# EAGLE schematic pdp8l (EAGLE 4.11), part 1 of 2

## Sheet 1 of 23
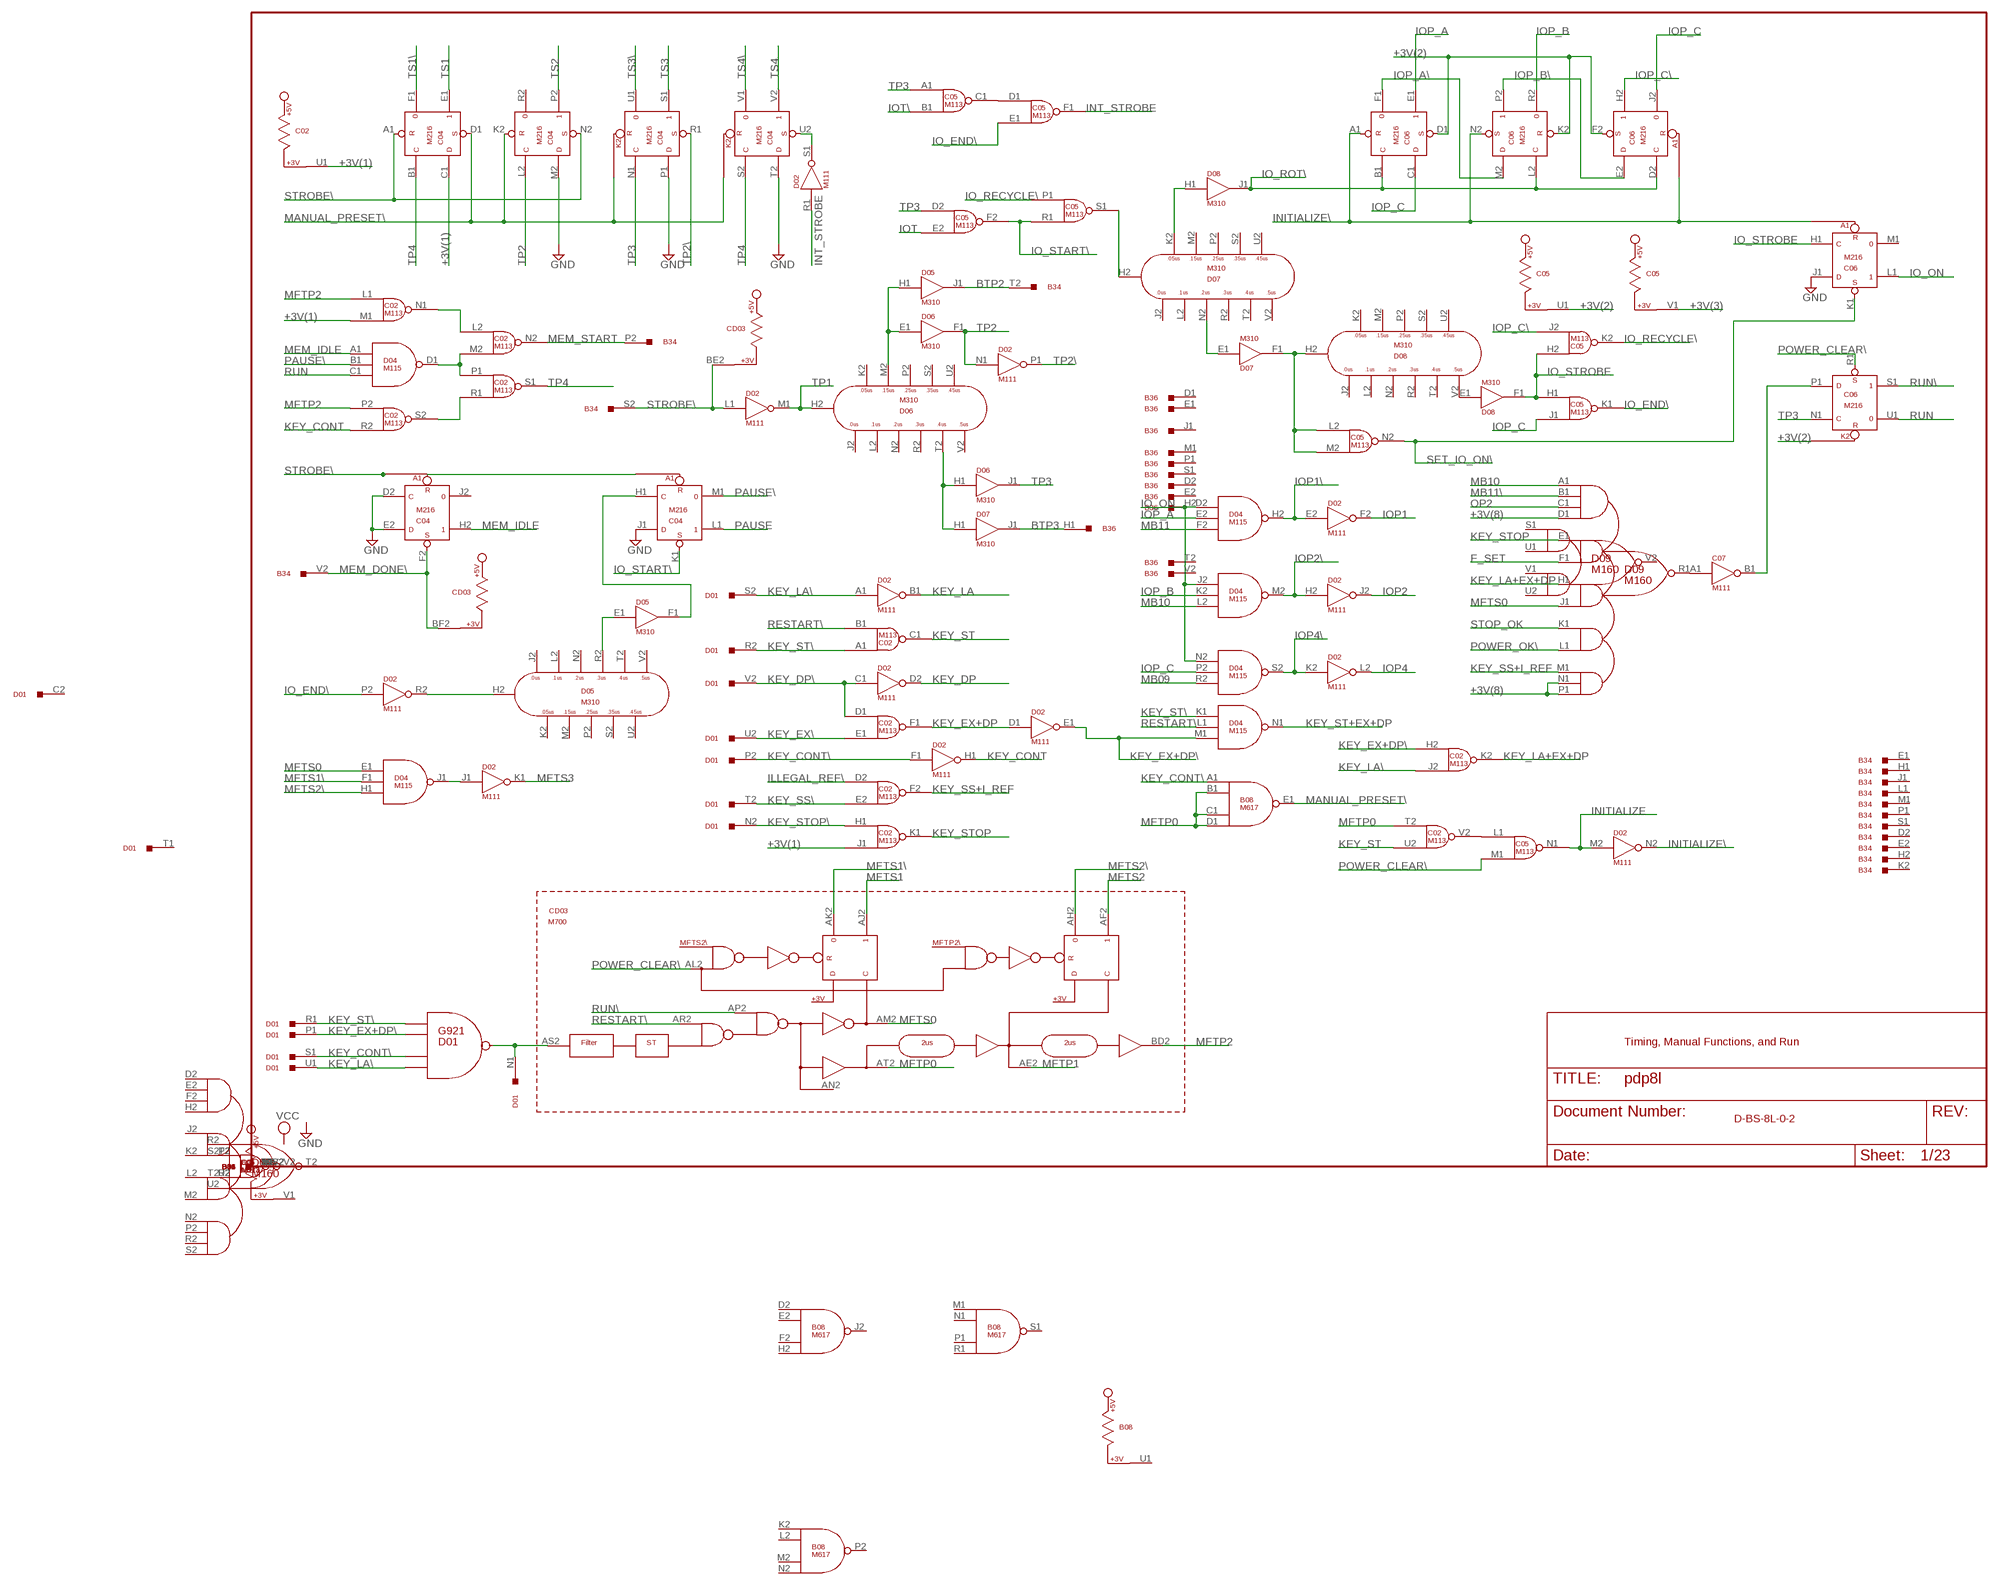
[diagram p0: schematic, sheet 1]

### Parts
B08  M617  [H807]
B34  M903  [H807]
B36  M903  [H807]
C02  M113  [H807]
C04  M216  M206X  [H807]
C05  M113  [H807]
C06  M216  M206X  [H807]
C07  M111  [H807]
CD03  M700  [H807-2]
D01  G921  M916  [H807]
D02  M111  [H807]
D04  M115  [H807]
D05  M310  [H807]
D06  M310  [H807]
D07  M310  [H807]
D08  M310  [H807]
D09  M160  [H807]

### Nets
+3V(1): C02.J1(K1:IN2) C02.M1(N1:IN2) C02.U1 C04.C1(E1:D) ; also sheet 2
+3V(2): C05.U1 C06.D1(E1:S) C06.F2(H2:S) C06.K2(P2:R)
+3V(3): C05.V1 ; also sheet 2
+3V(8): D09.D1(R1:IN1D) D09.N1(R1:IN5B) D09.P1(R1:IN5C) ; also sheet 3
BTP2: B34.T2 D05.J1(J1:OUT)
BTP3: B36.H1 D07.J1(J1:OUT)
F_SET: D09.F1(R1:IN2B) ; also sheet 2,3,6
GND [Supply]: C04.D2(H2:C) C04.E2(H2:D) C04.J1(L1:D) C04.M2(P2:D) C04.P1(S1:D) C04.T2(V2:D) C06.J1(L1:D) ; also sheet 3,8,9,10,11,12,13,14,15,16,19,20,21,23
ILLEGAL_REF\: C02.D2(F2:IN1) ; also sheet 2,5
INITIALIZE: C05.N1(N1:OUT) D02.M2(N2:IN) ; also sheet 12,13,14
INITIALIZE\: C06.A1(E1:R) C06.N2(P2:S) D02.N2(N2:OUT) ; also sheet 12,21,22
INT_STROBE: C05.F1(F1:OUT) D02.R1(S1:IN) ; also sheet 6
IO_END\: C05.E1(F1:IN2) C05.K1(K1:OUT) D02.P2(R2:IN)
IO_ON: C06.L1 D04.D2(H2:IN1) D04.J2(M2:IN1) D04.N2(S2:IN1)
IO_RECYCLE\: C05.K2(K2:OUT) C05.P1(S1:IN1)
IO_ROT\: C06.B1(E1:C) C06.D2(H2:C) C06.L2(P2:C) D08.J1(J1:OUT)
IO_START\: C04.K1(L1:S) C05.F2(F2:OUT) C05.R1(S1:IN2)
IO_STROBE: C05.H1(K1:IN1) C05.H2(K2:IN1) C06.H1(L1:C) D08.F1(F1:OUT) ; also sheet 5
IOP1: D02.F2(F2:OUT) ; also sheet 13,14,21,22,23
IOP1\: D02.E2(F2:IN) D04.H2(H2:OUT) ; also sheet 3,12
IOP2: D02.J2(J2:OUT) ; also sheet 13,14,20,21,22
IOP2\: D02.H2(J2:IN) D04.M2(M2:OUT) ; also sheet 3,12
IOP4: D02.L2(L2:OUT) ; also sheet 13,14,21,22,23
IOP4\: D02.K2(L2:IN) D04.S2(S2:OUT) ; also sheet 3,12
IOP_A: C06.E1 D04.E2(H2:IN2)
IOP_A\: C06.F1 C06.M2(P2:D)
IOP_B: C06.R2 D04.K2(M2:IN2)
IOP_B\: C06.E2(H2:D) C06.P2
IOP_C: C05.J1(K1:IN2) C06.C1(E1:D) C06.J2 D04.P2(S2:IN2)
IOP_C\: C05.J2(K2:IN2) C06.H2
IOT: C05.E2(F2:IN2) ; also sheet 2,6
IOT\: C05.B1(C1:IN2) ; also sheet 2
KEY_CONT: C02.R2(S2:IN2) D02.H1(H1:OUT)
KEY_CONT\: B08.A1(E1:IN1) D01.P2 D01.S1 D02.F1(H1:IN) ; also sheet 5
KEY_DP: D02.D2(D2:OUT) ; also sheet 3
KEY_DP\: C02.D1(F1:IN1) D01.V2 D02.C1(D2:IN)
KEY_EX+DP: C02.F1(F1:OUT) D02.D1(E1:IN) ; also sheet 3,4
KEY_EX+DP\: C02.H2(K2:IN1) D01.P1 D02.E1(E1:OUT) D04.M1(N1:IN3)
KEY_EX\: C02.E1(F1:IN2) D01.U2
KEY_LA: D02.B1(B1:OUT) ; also sheet 3,19
KEY_LA+EX+DP: C02.K2(K2:OUT) D09.H1(R1:IN3A) ; also sheet 5
KEY_LA\: C02.J2(K2:IN2) D01.S2 D01.U1 D02.A1(B1:IN) ; also sheet 19
KEY_SS+I_REF: C02.F2(F2:OUT) D09.M1(R1:IN5A)
KEY_SS\: C02.E2(F2:IN2) D01.T2
KEY_ST: C02.C1(C1:OUT) C02.U2(V2:IN2) ; also sheet 2,3
KEY_ST+EX+DP: D04.N1(N1:OUT) ; also sheet 3
KEY_ST\: C02.A1(C1:IN1) D01.R1 D01.R2 D04.K1(N1:IN1)
KEY_STOP: C02.K1(K1:OUT) D09.E1(R1:IN2A)
KEY_STOP\: C02.H1(K1:IN1) D01.N2
MANUAL_PRESET\: B08.E1(E1:OUT) C04.D1(E1:S) C04.K2(P2:R) ; also sheet 2,6
MB09: D04.R2(S2:IN3) ; also sheet 3,4,7,12,23
MB10: D04.L2(M2:IN3) D09.A1(R1:IN1A) ; also sheet 4,7,12,23
MB11: D04.F2(H2:IN3) ; also sheet 4,7,12,23
MB11\: D09.B1(R1:IN1B) ; also sheet 2,3,6,7,16,23
MEM_DONE\: B34.V2 C04.F2(H2:S) CD03.BF2 ; also sheet 6,15
MEM_IDLE: C04.H2 D04.A1(D1:IN1)
MEM_START: B34.P2 C02.N2(N2:OUT) ; also sheet 15
MFTP0: B08.B1(E1:IN2) B08.C1(E1:IN3) B08.D1(E1:IN4) C02.T2(V2:IN1) CD03.AT2(CT2) ; also sheet 19
MFTP1: CD03.AE2(CE2) ; also sheet 5,19
MFTP2: C02.L1(N1:IN1) C02.P2(S2:IN1) CD03.BD2(DD2) ; also sheet 2,5
MFTS0: CD03.AM2(CM2) D04.E1(J1:IN1) D09.J1(R1:IN3B)
MFTS1: CD03.AJ2(CJ2) ; also sheet 3
MFTS1\: CD03.AK2(CK2) D04.F1(J1:IN2) ; also sheet 3
MFTS2: CD03.AF2(CF2) ; also sheet 3,4
MFTS2\: CD03.AH2(CH2) D04.H1(J1:IN3) ; also sheet 3
MFTS3: D02.K1(K1:OUT) ; also sheet 3
N$1: C02.R1(S1:IN2) C02.S2(S2:OUT)
N$2: C02.L2(N2:IN1) C02.N1(N1:OUT)
N$3: C02.M2(N2:IN2) C02.P1(S1:IN1) D04.D1(D1:OUT)
N$4: D05.E1(F1:IN) D05.R2(H2:R2)
N$5: D02.R2(R2:OUT) D05.H2(H2:H2)
N$6: C04.H1(L1:C) D05.F1(F1:OUT)
N$7: D02.J1(K1:IN) D04.J1(J1:OUT)
N$8: D05.H1(J1:IN) D06.E1(F1:IN) D06.M2(H2:M2)
N$9: D06.H1(J1:IN) D06.T2(H2:T2) D07.H1(J1:IN)
N$10: C05.S1(S1:OUT) D07.H2(H2:H2)
N$11: C04.U2(V2:S) D02.S1(S1:OUT)
N$12: C05.C1(C1:OUT) C05.D1(F1:IN1)
N$13: D07.K2(H2:K2) D08.H1(J1:IN)
N$14: D07.E1(F1:IN) D07.N2(H2:N2)
N$15: C05.L2(N2:IN1) C05.M2(N2:IN2) D07.F1(F1:OUT) D08.H2(H2:H2)
N$16: D08.E1(F1:IN) D08.V2(H2:V2)
N$19: C07.A1(B1:IN) D09.R1(R1:OUT)
N$20: C06.P1(S1:D) C07.B1(B1:OUT)
N$21: C02.V2(V2:OUT) C05.L1(N1:IN1)
N$22: CD03.AS2(CS2) D01.N1
OP2: D09.C1(R1:IN1C) ; also sheet 2,3,5
PAUSE: C04.L1 ; also sheet 3
PAUSE\: C04.M1 D04.B1(D1:IN2)
POWER_CLEAR\: C05.M1(N1:IN2) C06.R1(S1:S) CD03.AL2(CL2) ; also sheet 15
POWER_OK\: D09.L1(R1:IN4B) ; also sheet 15
RESTART\: C02.B1(C1:IN2) CD03.AR2(CR2) D04.L1(N1:IN2) ; also sheet 3,19,20
RUN: C06.U1 D04.C1(D1:IN3)
RUN\: C06.S1 CD03.AP2(CP2) ; also sheet 12
SET_IO_ON\: C05.N2(N2:OUT) C06.K1(L1:S) ; also sheet 5
STOP_OK: D09.K1(R1:IN4A) ; also sheet 15,20
STROBE\: B34.S2 C04.A1(E1:R) C04.N2(P2:S) CD03.BE2 D02.L1(M1:IN) ; also sheet 6,15
TP1: D02.M1(M1:OUT) D06.H2(H2:H2) ; also sheet 2,5,6
TP2: C04.L2(P2:C) D02.N1(P1:IN) D06.F1(F1:OUT) ; also sheet 2,5,6
TP2\: C04.R1(S1:S) D02.P1(P1:OUT) ; also sheet 5
TP3: C04.N1(S1:C) C05.A1(C1:IN1) C05.D2(F2:IN1) C06.N1(S1:C) D06.J1(J1:OUT) ; also sheet 5,23
TP4: C02.S1(S1:OUT) C04.B1(E1:C) C04.S2(V2:C) ; also sheet 2,5,6
TS1: C04.E1 ; also sheet 3,4
TS1\: C04.F1 ; also sheet 12
TS2: C04.P2 ; also sheet 2,3,4,5
TS3: C04.S1 ; also sheet 2,3,4
TS3\: C04.U1 ; also sheet 12
TS4: C04.V2 ; also sheet 3,19
TS4\: C04.V1 ; also sheet 3
Unconnected: B34.M2 B36.K2 B36.M2 B36.P2 C02.V1 C04.J2 C04.R2 CD03.AN2(CN2) D01.A1 D01.B1 D01.B2 D01.C1 D01.D1 D01.E1 D01.F1 D01.H1 D01.H2 D01.J1 D01.K1 D01.L1 D01.M1 D05.J2(H2:J2) D05.K2(H2:K2) D05.L2(H2:L2) D05.M2(H2:M2) D05.N2(H2:N2) D05.P2(H2:P2) D05.S2(H2:S2) D05.T2(H2:T2) D05.U2(H2:U2) D05.V2(H2:V2) D06.J2(H2:J2) D06.K2(H2:K2) D06.L2(H2:L2) D06.N2(H2:N2) D06.P2(H2:P2) D06.R2(H2:R2) D06.S2(H2:S2) D06.U2(H2:U2) D06.V2(H2:V2) D07.J2(H2:J2) D07.L2(H2:L2) D07.M2(H2:M2) D07.P2(H2:P2) D07.R2(H2:R2) D07.S2(H2:S2) D07.T2(H2:T2) D07.U2(H2:U2) D07.V2(H2:V2) D08.J2(H2:J2) D08.K2(H2:K2) D08.L2(H2:L2) D08.M2(H2:M2) D08.N2(H2:N2) D08.P2(H2:P2) D08.R2(H2:R2) D08.S2(H2:S2) D08.T2(H2:T2) D08.U2(H2:U2)

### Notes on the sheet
- G921
- D01 | Timing, Manual Functions, and Run
- D-BS-8L-0-2

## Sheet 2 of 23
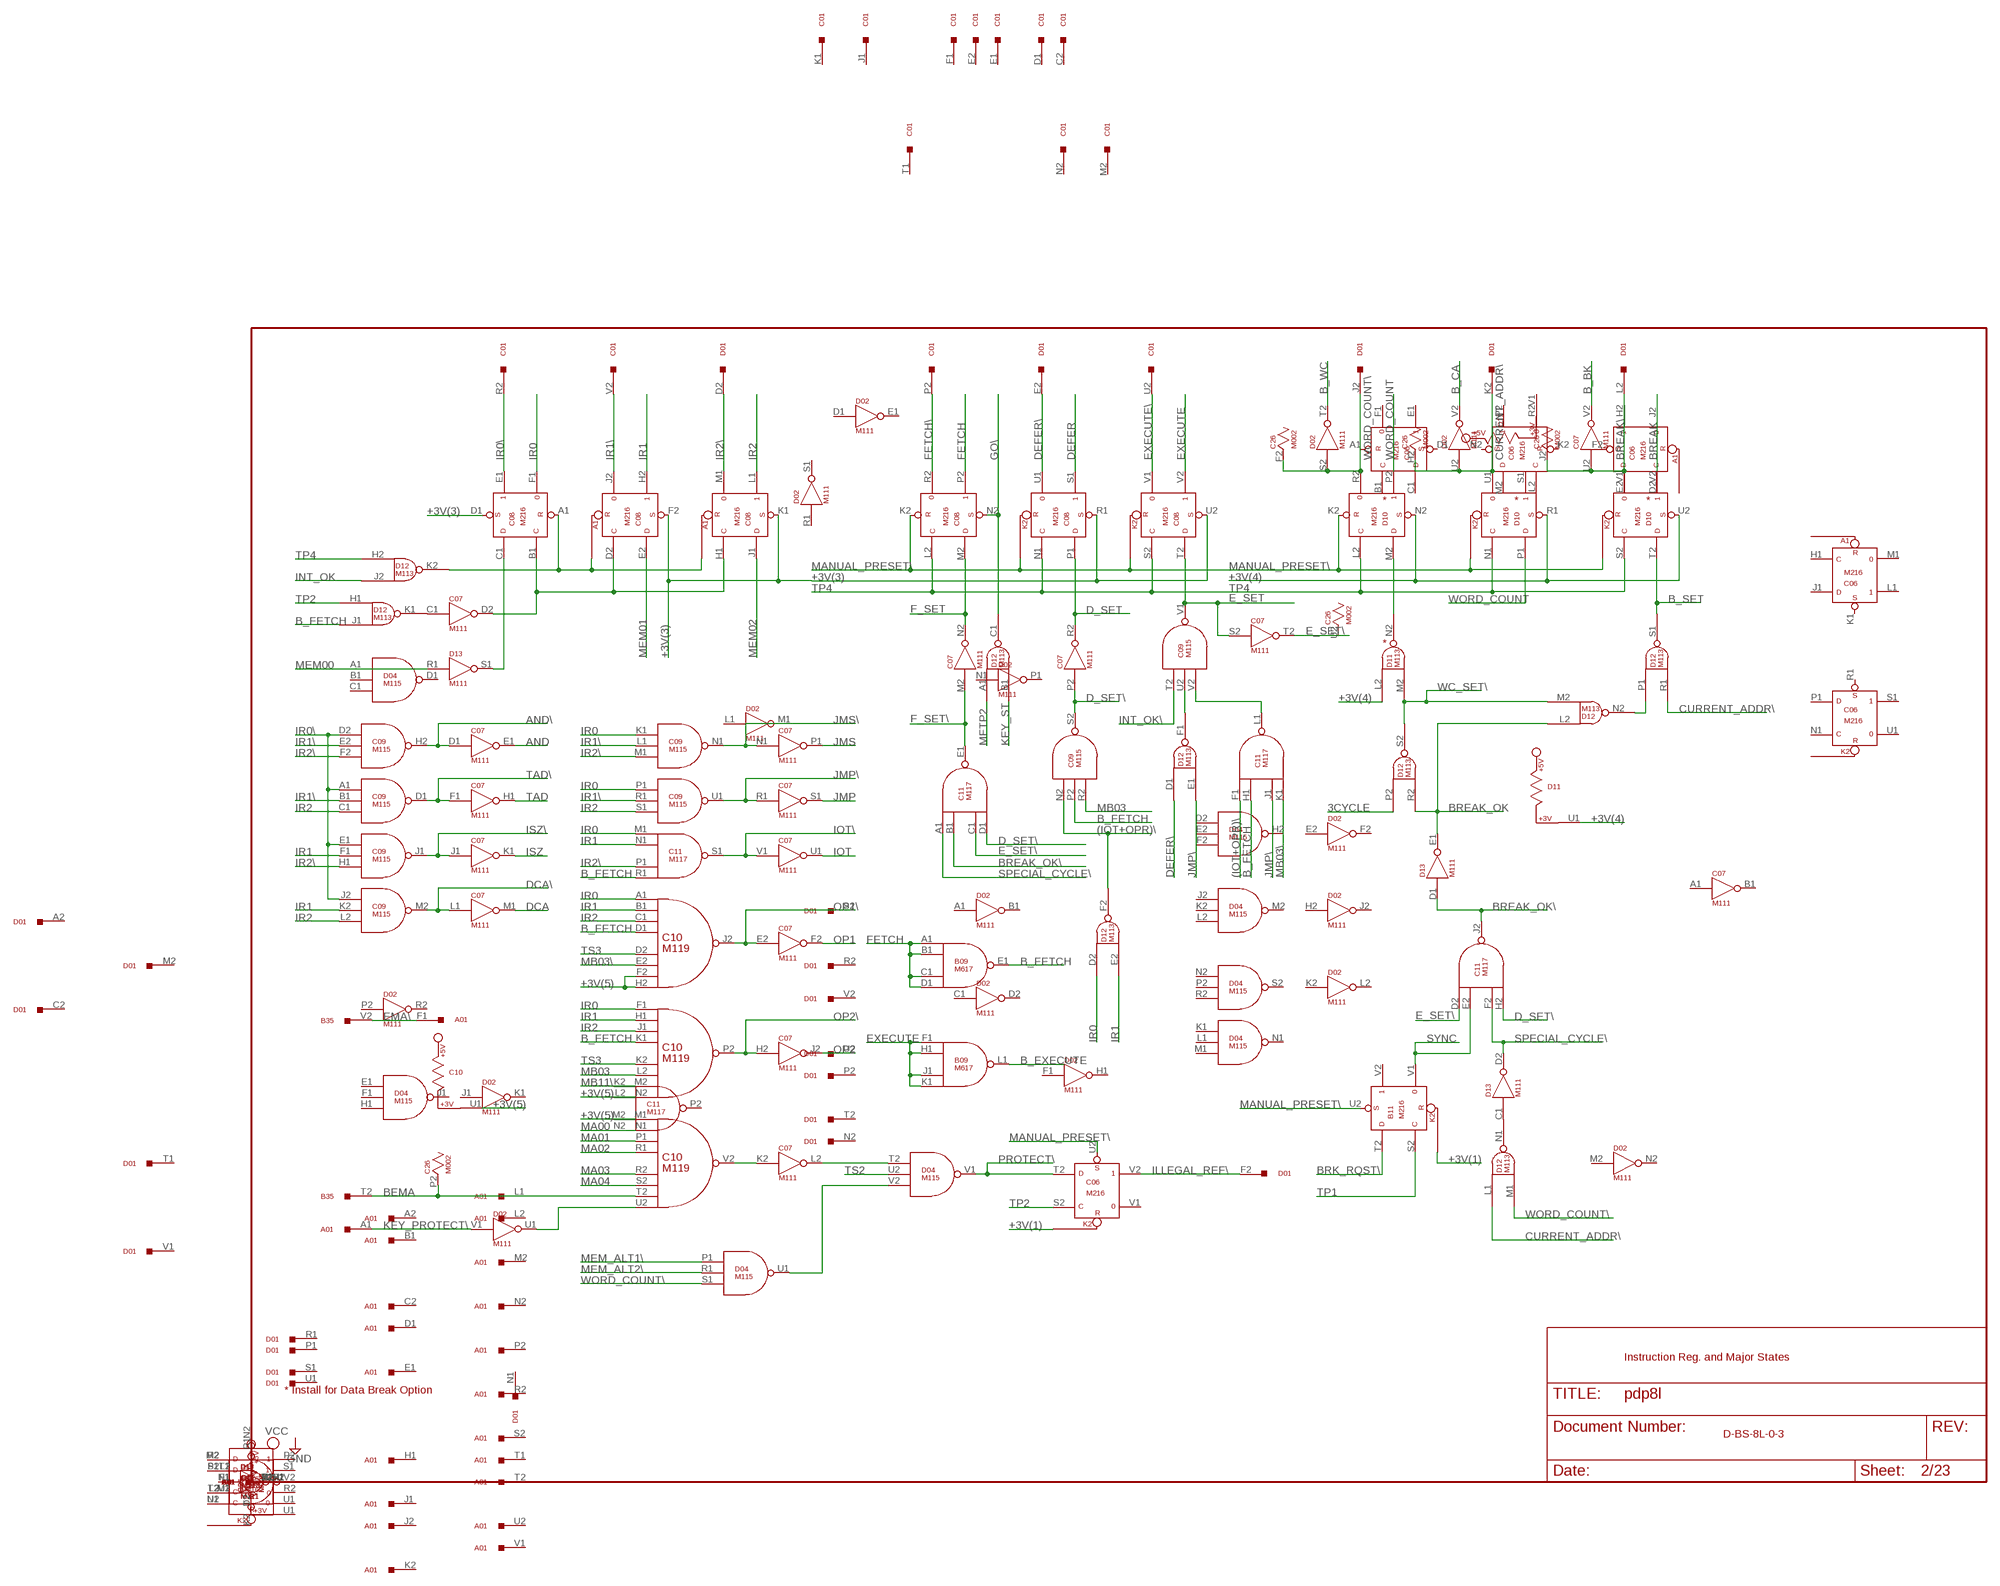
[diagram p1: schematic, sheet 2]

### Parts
A01  G921  M916  [H807]
B09  M617  [H807]
B11  M216  M206X  [H807]
B35  M903  [H807]
C01  G921  M916  [H807]
C08  M216  M206X  [H807]
C09  M115  [H807]
C10  M119  [H807]
C11  M117  [H807]
C26  M002  [H807]
D10  M216  M206X  [H807]
D11  M113  [H807]
D12  M113  [H807]
D13  M111  [H807]

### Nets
3CYCLE: D12.P2(S2:IN1) ; also sheet 12
(IOT+OPR)\: C09.N2(S2:IN1) C11.F1(L1:IN1) D12.F2(F2:OUT)
+3V(3): C08.D1(E1:S) C08.F2(H2:S) C08.K1(L1:S) C08.R1(S1:S) C08.U2(V2:S) ; also sheet 1
+3V(4): D10.N2(P2:S) D10.R1(S1:S) D10.U2(V2:S) D11.L2(N2:IN1) D11.U1 ; also sheet 6
+3V(5): C10.F2(J2:IN7) C10.H2(J2:IN8) C10.M1(V2:IN1) C10.N2(P2:IN8) C10.U1
AND: C07.E1(E1:OUT) ; also sheet 4
AND\: C07.D1(E1:IN) C09.H2(H2:OUT) ; also sheet 5
B_BK: C07.V2(V2:OUT) ; also sheet 3,4
B_CA: D02.V2(V2:OUT) ; also sheet 3,4
B_EXECUTE: B09.L1(L1:OUT) ; also sheet 3,4,5
B_FETCH: B09.E1(E1:OUT) C09.P2(S2:IN2) C10.D1(J2:IN4) C10.K1(P2:IN4) C11.H1(L1:IN2) C11.R1(S1:IN4) D12.J1(K1:IN2) ; also sheet 3,5,6
B_SET: D10.T2(V2:D) D12.S1(S1:OUT) ; also sheet 19
B_WC: D02.T2(T2:OUT) ; also sheet 3
BEMA: B35.T2 C10.T2(V2:IN7) C26.P2
BREAK: D10.V2 ; also sheet 6
BREAK\: C07.U2(V2:IN) C26.J2 D01.L2 D10.V1 ; also sheet 12
BREAK_OK: D12.L2(N2:IN1) D12.R2(S2:IN2) D13.E1(E1:OUT) ; also sheet 3
BREAK_OK\: C11.B1(E1:IN2) C11.J2(J2:OUT) D13.D1(E1:IN) ; also sheet 6
BRK_RQST\: B11.T2(V2:D) ; also sheet 12
CURRENT_ADDR\: C26.H2 D01.K2 D02.U2(V2:IN) D10.U1 D12.L1(N1:IN1) D12.R1(S1:IN2)
D_SET: C07.R2(R2:OUT) C08.P1(S1:D)
D_SET\: C07.P2(R2:IN) C09.S2(S2:OUT) C11.D1(E1:IN4) C11.H2(J2:IN4) ; also sheet 3
DCA: C07.M1(M1:OUT) ; also sheet 3
DCA\: C07.L1(M1:IN) C09.M2(M2:OUT) ; also sheet 5
DEFER: C08.S1 ; also sheet 3,4,5,19
DEFER\: C08.U1 D01.E2 D12.D1(F1:IN1)
E_SET: C07.S2(T2:IN) C08.T2(V2:D) C09.V1(V1:OUT)
E_SET\: C07.T2(T2:OUT) C11.C1(E1:IN3) C11.D2(J2:IN1) ; also sheet 3,19
EMA\: A01.F1 B35.V2
EXECUTE: B09.F1(L1:IN1) B09.H1(L1:IN2) B09.J1(L1:IN3) B09.K1(L1:IN4) C08.V2
EXECUTE\: C01.U2 C08.V1
F_SET: C07.N2(N2:OUT) C08.M2(P2:D) ; also sheet 1,3,6
F_SET\: C07.M2(N2:IN) C11.E1(E1:OUT) ; also sheet 19
FETCH: B09.A1(E1:IN1) B09.B1(E1:IN2) B09.C1(E1:IN3) B09.D1(E1:IN4) C08.P2 ; also sheet 4
FETCH\: C01.P2 C08.R2
GO\: C08.N2(P2:S) D12.C1(C1:OUT) ; also sheet 5,6
ILLEGAL_REF\: C06.V2 D01.F2 ; also sheet 1,5
INT_OK: D12.J2(K2:IN2) ; also sheet 6,19
INT_OK\: C09.T2(V1:IN1) ; also sheet 3,6
IOT: C07.U1(U1:OUT) ; also sheet 1,6
IOT\: C07.V1(U1:IN) C11.S1(S1:OUT) ; also sheet 1
IR0: C08.F1 C09.K1(N1:IN1) C09.P1(U1:IN1) C10.A1(J2:IN1) C10.F1(P2:IN1) C11.M1(S1:IN1) D12.D2(F2:IN1)
IR0\: C01.R2 C08.E1 C09.A1(D1:IN1) C09.D2(H2:IN1) C09.E1(J1:IN1) C09.J2(M2:IN1) ; also sheet 19
IR1: C08.H2 C09.F1(J1:IN2) C09.K2(M2:IN2) C10.B1(J2:IN2) C10.H1(P2:IN2) C11.N1(S1:IN2) D12.E2(F2:IN2)
IR1\: C01.V2 C08.J2 C09.B1(D1:IN2) C09.E2(H2:IN2) C09.L1(N1:IN2) C09.R1(U1:IN2)
IR2: C08.L1 C09.C1(D1:IN3) C09.L2(M2:IN3) C09.S1(U1:IN3) C10.C1(J2:IN3) C10.J1(P2:IN3)
IR2\: C08.M1 C09.F2(H2:IN3) C09.H1(J1:IN3) C09.M1(N1:IN3) C11.P1(S1:IN3) D01.D2
ISZ: C07.K1(K1:OUT) ; also sheet 4,5
ISZ\: C07.J1(K1:IN) C09.J1(J1:OUT)
JMP: C07.S1(S1:OUT) ; also sheet 3,5
JMP\: C07.R1(S1:IN) C09.U1(U1:OUT) C11.J1(L1:IN3) D12.E1(F1:IN2) ; also sheet 3,19
JMS: C07.P1(P1:OUT) ; also sheet 3,4,5
JMS\: C07.N1(P1:IN) C09.N1(N1:OUT) ; also sheet 19
KEY_PROTECT\: A01.A1 D02.V1(U1:IN)
KEY_ST: D12.B1(C1:IN2) ; also sheet 1,3
MA00: C10.N1(V2:IN2) ; also sheet 7,17
MA01: C10.P1(V2:IN3) ; also sheet 7,17
MA02: C10.R1(V2:IN4) ; also sheet 7,17
MA03: C10.R2(V2:IN5) ; also sheet 7,17
MA04: C10.S2(V2:IN6) ; also sheet 7,17
MANUAL_PRESET\: B11.U2(V2:S) C06.U2(V2:S) C08.K2(P2:R) D10.K2(P2:R) ; also sheet 1,6
MB03: C09.R2(S2:IN3) C10.L2(P2:IN6) ; also sheet 7,12,23
MB03\: C10.E2(J2:IN6) C11.K1(L1:IN4) ; also sheet 3,6,7,12,13,14,16,20,21,22,23
MB11\: C10.M2(P2:IN7) ; also sheet 1,3,6,7,16,23
MEM00: D13.R1(S1:IN) ; also sheet 8,16,23
MEM01: C08.E2(H2:D) ; also sheet 8,16,23
MEM02: C08.J1(L1:D) ; also sheet 8,16,23
MEM_ALT1\: D04.P1(U1:IN1) ; also sheet 3
MEM_ALT2\: D04.R1(U1:IN2) ; also sheet 4
MFTP2: D12.A1(C1:IN1) ; also sheet 1,5
N$23: C07.C1(D2:IN) D12.K1(K1:OUT)
N$24: D10.M2(P2:D) D11.N2(N2:OUT)
N$25: D12.N2(N2:OUT) D12.P1(S1:IN1)
N$26: C07.D2(D2:OUT) C08.B1(E1:C) C08.D2(H2:C) C08.H1(L1:C)
N$27: C08.A1(E1:R) D12.K2(K2:OUT)
N$28: C08.C1(E1:D) D13.S1(S1:OUT)
N$29: C10.U2(V2:IN8) D02.U1(U1:OUT)
N$30: C07.L2(L2:OUT) D04.T2(V1:IN1)
N$31: D04.U1(U1:OUT) D04.V2(V1:IN3)
N$32: C07.K2(L2:IN) C10.V2(V2:OUT)
N$36: D12.N1(N1:OUT) D13.C1(D2:IN)
N$37: C09.U2(V1:IN2) D12.F1(F1:OUT)
N$38: C09.V2(V1:IN3) C11.L1(L1:OUT)
OP1: C07.F2(F2:OUT) ; also sheet 3,4
OP1\: C07.E2(F2:IN) C10.J2(J2:OUT) ; also sheet 5
OP2: C07.J2(J2:OUT) ; also sheet 1,3,5
OP2\: C07.H2(J2:IN) C10.P2(P2:OUT) ; also sheet 5
PROTECT\: C06.T2(V2:D) D04.V1(V1:OUT) ; also sheet 3,4
SPECIAL_CYCLE\: C11.A1(E1:IN1) C11.F2(J2:IN3) D13.D2(D2:OUT)
SYNC: B11.V1 C11.E2(J2:IN2)
TAD: C07.H1(H1:OUT) ; also sheet 3
TAD\: C07.F1(H1:IN) C09.D1(D1:OUT) ; also sheet 5
TP1: B11.S2(V2:C) ; also sheet 1,5,6
TP2: C06.S2(V2:C) D12.H1(K1:IN1) ; also sheet 1,5,6
TP4: C08.L2(P2:C) C08.N1(S1:C) C08.S2(V2:C) D10.L2(P2:C) D10.N1(S1:C) D10.S2(V2:C) D12.H2(K2:IN1) ; also sheet 1,5,6
TS2: D04.U2(V1:IN2) ; also sheet 1,3,4,5
TS3: C10.D2(J2:IN5) C10.K2(P2:IN5) ; also sheet 1,3,4
WC_SET\: D11.M2(N2:IN2) D12.M2(N2:IN2) D12.S2(S2:OUT) ; also sheet 19
WORD_COUNT: D10.P1(S1:D) D10.P2
WORD_COUNT\: C26.F2 D01.J2 D02.S2(T2:IN) D04.S1(U1:IN3) D10.R2 D12.M1(N1:IN2) ; also sheet 4,6,19
Unconnected: A01.M1 A01.N1 A01.P1 A01.R1 A01.S1 A01.U1 A01.V2 B11.V2 B35.M2 B35.P2 B35.S2 C01.A1 C01.B1 C01.B2 C01.C1 C01.D2 C01.L1 C01.M1 C01.N1 C01.P1 C01.R1 C01.S1 C01.T2 C01.U1 C06.M1 C06.V1 C10.V1 C11.U1 C11.V1 C26.K2 C26.L2 C26.M2 C26.N2 D10.H1(L1:C) D10.J1(L1:D) D10.K1(L1:S) D10.L1 D10.M1 D10.S1 D12.U1 D12.V1

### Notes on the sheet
- * | * | *
- *
- Instruction Reg. and Major States
- * Install for Data Break Option
- D-BS-8L-0-3

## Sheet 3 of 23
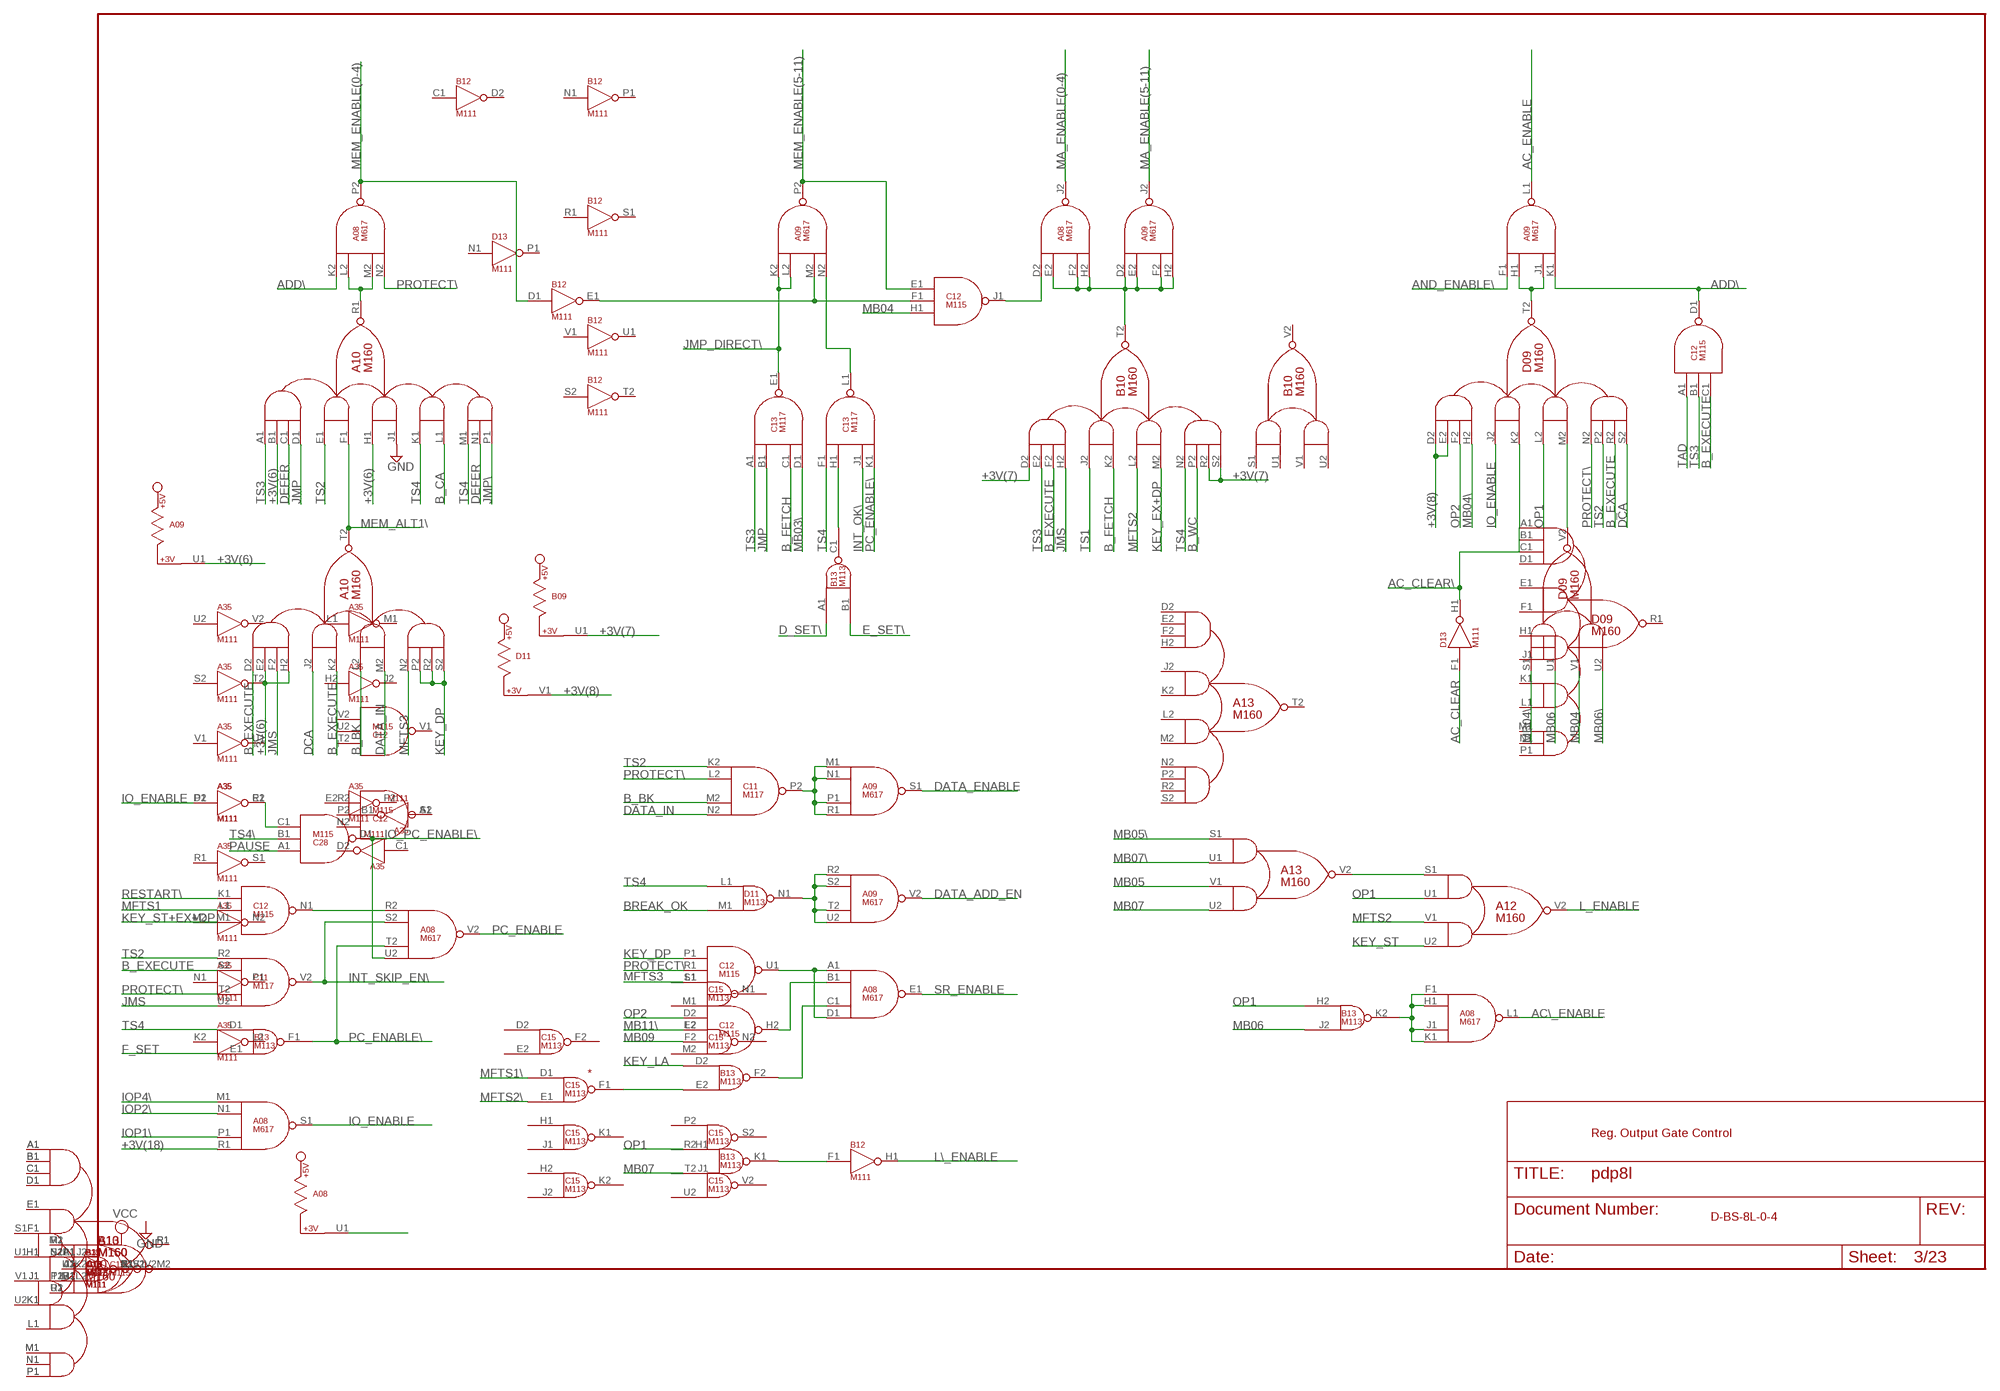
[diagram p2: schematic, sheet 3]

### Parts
A08  M617  [H807]
A09  M617  [H807]
A10  M160  [H807]
A12  M160  [H807]
A13  M160  [H807]
A35  M111  [H807]
B10  M160  [H807]
B12  M111  [H807]
B13  M113  [H807]
C12  M115  [H807]
C13  M117  [H807]
C15  M113  [H807]
C28  M115  [H807]

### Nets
+3V(6): A09.U1 A10.B1(R1:IN1B) A10.E2(T2:IN1B) A10.H1(R1:IN3A) A10.H2(T2:IN1D)
+3V(7): B09.U1 B10.D2(T2:IN1A) B10.R2(T2:IN4C) B10.S2(T2:IN4D)
+3V(8): D09.D2(T2:IN1A) D09.E2(T2:IN1B) D11.V1 ; also sheet 1
+3V(18): A08.R1(S1:IN4) A08.U1
AC\_ENABLE: A08.L1(L1:OUT) ; also sheet 8,9,10,11
AC_CLEAR: D13.F1(H1:IN) ; also sheet 12
AC_CLEAR\: D09.K2(T2:IN2B) D13.H1(H1:OUT)
AC_ENABLE: A09.L1(L1:OUT) ; also sheet 8,9,10,11
ADD\: A08.K2(P2:IN1) A09.K1(L1:IN4) C12.D1(D1:OUT)
AND_ENABLE\: A09.F1(L1:IN1) ; also sheet 4
B_BK: A10.L2(T2:IN3A) C11.M2(P2:IN3) ; also sheet 2,4
B_CA: A10.L1(R1:IN4B) ; also sheet 2,4
B_EXECUTE: A10.D2(T2:IN1A) A10.K2(T2:IN2B) B10.F2(T2:IN1C) C11.S2(V2:IN2) C12.C1(D1:IN3) D09.R2(T2:IN4C) ; also sheet 2,4,5
B_FETCH: B10.K2(T2:IN2B) C13.C1(E1:IN3) ; also sheet 2,5,6
B_WC: B10.P2(T2:IN4B) ; also sheet 2
BREAK_OK: D11.M1(N1:IN2) ; also sheet 2
D_SET\: B13.A1(C1:IN1) ; also sheet 2
DATA_ADD_EN: A09.V2(V2:OUT) ; also sheet 8,9,10,11
DATA_ENABLE: A09.S1(S1:OUT) ; also sheet 8,9,10,11
DATA_IN: A10.M2(T2:IN3B) C11.N2(P2:IN4) ; also sheet 12
DCA: A10.J2(T2:IN2A) D09.S2(T2:IN4D) ; also sheet 2
DEFER: A10.C1(R1:IN1C) A10.N1(R1:IN5B) ; also sheet 2,4,5,19
E_SET\: B13.B1(C1:IN2) ; also sheet 2,19
F_SET: B13.E1(F1:IN2) ; also sheet 1,2,6
GND [Supply]: A10.J1(R1:IN3B) ; also sheet 1,8,9,10,11,12,13,14,15,16,19,20,21,23
INT_OK\: C13.J1(L1:IN3) ; also sheet 2,6
INT_SKIP_EN\: A08.S2(V2:IN2) C11.V2(V2:OUT) ; also sheet 4
IO_ENABLE: A08.S1(S1:OUT) A35.D1(E1:IN) D09.J2(T2:IN2A) ; also sheet 5,8,9,10,11
IO_PC_ENABLE\: A08.U2(V2:IN4) C28.D1(D1:OUT) ; also sheet 4
IOP1\: A08.P1(S1:IN3) ; also sheet 1,12
IOP2\: A08.N1(S1:IN2) ; also sheet 1,12
IOP4\: A08.M1(S1:IN1) ; also sheet 1,12
JMP: A10.D1(R1:IN1D) C13.B1(E1:IN2) ; also sheet 2,5
JMP\: A10.P1(R1:IN5C) ; also sheet 2,19
JMP_DIRECT\: A09.K2(P2:IN1) A09.L2(P2:IN2) C13.E1(E1:OUT) ; also sheet 5
JMS: A10.F2(T2:IN1C) B10.H2(T2:IN1D) C11.U2(V2:IN4) ; also sheet 2,4,5
KEY_DP: A10.P2(T2:IN4B) A10.R2(T2:IN4C) A10.S2(T2:IN4D) C12.P1(U1:IN1) ; also sheet 1
KEY_EX+DP: B10.M2(T2:IN3B) ; also sheet 1,4
KEY_LA: B13.D2(F2:IN1) ; also sheet 1,19
KEY_ST: A12.U2(V2:IN2B) ; also sheet 1,2
KEY_ST+EX+DP: C12.M1(N1:IN3) ; also sheet 1
L\_ENABLE: B12.H1(H1:OUT) ; also sheet 7
L_ENABLE: A12.V2(V2:OUT) ; also sheet 7
MA_ENABLE(0-4): A08.J2(J2:OUT) ; also sheet 8,9
MA_ENABLE(5-11): A09.J2(J2:OUT) ; also sheet 9,10,11
MB03\: C13.D1(E1:IN4) ; also sheet 2,6,7,12,13,14,16,20,21,22,23
MB04: C12.H1(J1:IN3) D09.V1(V2:IN2A) ; also sheet 7,12,23
MB04\: D09.H2(T2:IN1D) D09.S1(V2:IN1A) ; also sheet 6,7,12,13,14,20,21,22,23
MB05: A13.V1(V2:IN2A) ; also sheet 5,7,12,20,23
MB05\: A13.S1(V2:IN1A) ; also sheet 6,7,12,13,14,21,22,23
MB06: B13.J2(K2:IN2) D09.U1(V2:IN1B) ; also sheet 5,7,12,14,23
MB06\: D09.U2(V2:IN2B) ; also sheet 6,7,12,13,20,21,22,23
MB07: A13.U2(V2:IN2B) B13.J1(K1:IN2) ; also sheet 5,7,12,13,21,23
MB07\: A13.U1(V2:IN1B) ; also sheet 6,7,12,14,20,22,23
MB09: C12.F2(H2:IN3) ; also sheet 1,4,7,12,23
MB11\: C12.E2(H2:IN2) ; also sheet 1,2,6,7,16,23
MEM_ALT1\: A10.F1(R1:IN2B) A10.T2(T2:OUT) ; also sheet 2
MEM_ENABLE(0-4): A08.P2(P2:OUT) B12.D1(E1:IN) ; also sheet 4,8,9
MEM_ENABLE(5-11): A09.P2(P2:OUT) C12.E1(J1:IN1) ; also sheet 9,10,11
MFTS1: C12.L1(N1:IN2) ; also sheet 1
MFTS1\: C15.D1(F1:IN1) ; also sheet 1
MFTS2: A12.V1(V2:IN2A) B10.L2(T2:IN3A) ; also sheet 1,4
MFTS2\: C15.E1(F1:IN2) ; also sheet 1
MFTS3: A10.N2(T2:IN4A) C12.S1(U1:IN3) ; also sheet 1
N$39: A08.L2(P2:IN2) A08.M2(P2:IN3) A10.R1(R1:OUT)
N$40: A35.E1(E1:OUT) C28.C1(D1:IN3)
N$41: A09.M2(P2:IN3) B12.E1(E1:OUT) C12.F1(J1:IN2)
N$42: A08.D2(J2:IN1) C12.J1(J1:OUT)
N$43: A08.R2(V2:IN1) C12.N1(N1:OUT)
N$44: A09.N2(P2:IN4) C13.L1(L1:OUT)
N$45: A08.E2(J2:IN2) A08.F2(J2:IN3) A08.H2(J2:IN4) A09.D2(J2:IN1) A09.E2(J2:IN2) A09.F2(J2:IN3) A09.H2(J2:IN4) B10.T2(T2:OUT)
N$46: B13.C1(C1:OUT) C13.H1(L1:IN2)
N$47: A09.H1(L1:IN2) A09.J1(L1:IN3) D09.T2(T2:OUT)
N$48: D09.M2(T2:IN3B) D09.V2(V2:OUT)
N$49: A09.R2(V2:IN1) A09.S2(V2:IN2) A09.T2(V2:IN3) A09.U2(V2:IN4) D11.N1(N1:OUT)
N$50: A09.M1(S1:IN1) A09.N1(S1:IN2) A09.P1(S1:IN3) A09.R1(S1:IN4) C11.P2(P2:OUT)
N$51: A08.A1(E1:IN1) A08.D1(E1:IN4) C12.U1(U1:OUT)
N$52: B12.F1(H1:IN) B13.K1(K1:OUT)
N$53: B13.E2(F2:IN2) C15.F1(F1:OUT)
N$55: A12.S1(V2:IN1A) A13.V2(V2:OUT)
N$56: A08.F1(L1:IN1) A08.H1(L1:IN2) A08.J1(L1:IN3) A08.K1(L1:IN4) B13.K2(K2:OUT)
N$63: A08.B1(E1:IN2) C12.H2(H2:OUT)
N$64: A08.C1(E1:IN3) B13.F2(F2:OUT)
OP1: A12.U1(V2:IN1B) B13.H1(K1:IN1) B13.H2(K2:IN1) D09.L2(T2:IN3A) ; also sheet 2,4
OP2: C12.D2(H2:IN1) D09.F2(T2:IN1C) ; also sheet 1,2,5
PAUSE: C28.A1(D1:IN1) ; also sheet 1
PC_ENABLE: A08.V2(V2:OUT) ; also sheet 8,9,10,11
PC_ENABLE\: A08.T2(V2:IN3) B13.F1(F1:OUT) C13.K1(L1:IN4) ; also sheet 4
PROTECT\: A08.N2(P2:IN4) C11.L2(P2:IN2) C11.T2(V2:IN3) C12.R1(U1:IN2) D09.N2(T2:IN4A) ; also sheet 2,4
RESTART\: C12.K1(N1:IN1) ; also sheet 1,19,20
SR_ENABLE: A08.E1(E1:OUT) ; also sheet 8,9,10,11
TAD: C12.A1(D1:IN1) ; also sheet 2
TS1: B10.J2(T2:IN2A) ; also sheet 1,4
TS2: A10.E1(R1:IN2A) C11.K2(P2:IN1) C11.R2(V2:IN1) D09.P2(T2:IN4B) ; also sheet 1,2,4,5
TS3: A10.A1(R1:IN1A) B10.E2(T2:IN1B) C12.B1(D1:IN2) C13.A1(E1:IN1) ; also sheet 1,2,4
TS4: A10.K1(R1:IN4A) A10.M1(R1:IN5A) B10.N2(T2:IN4A) B13.D1(F1:IN1) C13.F1(L1:IN1) D11.L1(N1:IN1) ; also sheet 1,19
TS4\: C28.B1(D1:IN2) ; also sheet 1
Unconnected: A08.V1 A35.F1(H1:IN) A35.H1(H1:OUT) B13.P1(S1:IN1) B13.R1(S1:IN2) B13.S1(S1:OUT) B13.U1 B13.V1 C13.U1 C13.V1 C15.U1 C15.V1 C28.E1(J1:IN1) C28.F1(J1:IN2) C28.H1(J1:IN3) C28.J1(J1:OUT) C28.J2(M2:IN1) C28.K1(N1:IN1) C28.K2(M2:IN2) C28.L1(N1:IN2) C28.L2(M2:IN3) C28.M1(N1:IN3) C28.M2(M2:OUT) C28.N1(N1:OUT) C28.N2(S2:IN1) C28.P1(U1:IN1) C28.P2(S2:IN2) C28.R1(U1:IN2) C28.R2(S2:IN3) C28.S1(U1:IN3) C28.S2(S2:OUT) C28.T2(V1:IN1) C28.U1(U1:OUT) C28.U2(V1:IN2) C28.V1(V1:OUT) C28.V2(V1:IN3)

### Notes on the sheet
- *
- Reg. Output Gate Control
- D-BS-8L-0-4

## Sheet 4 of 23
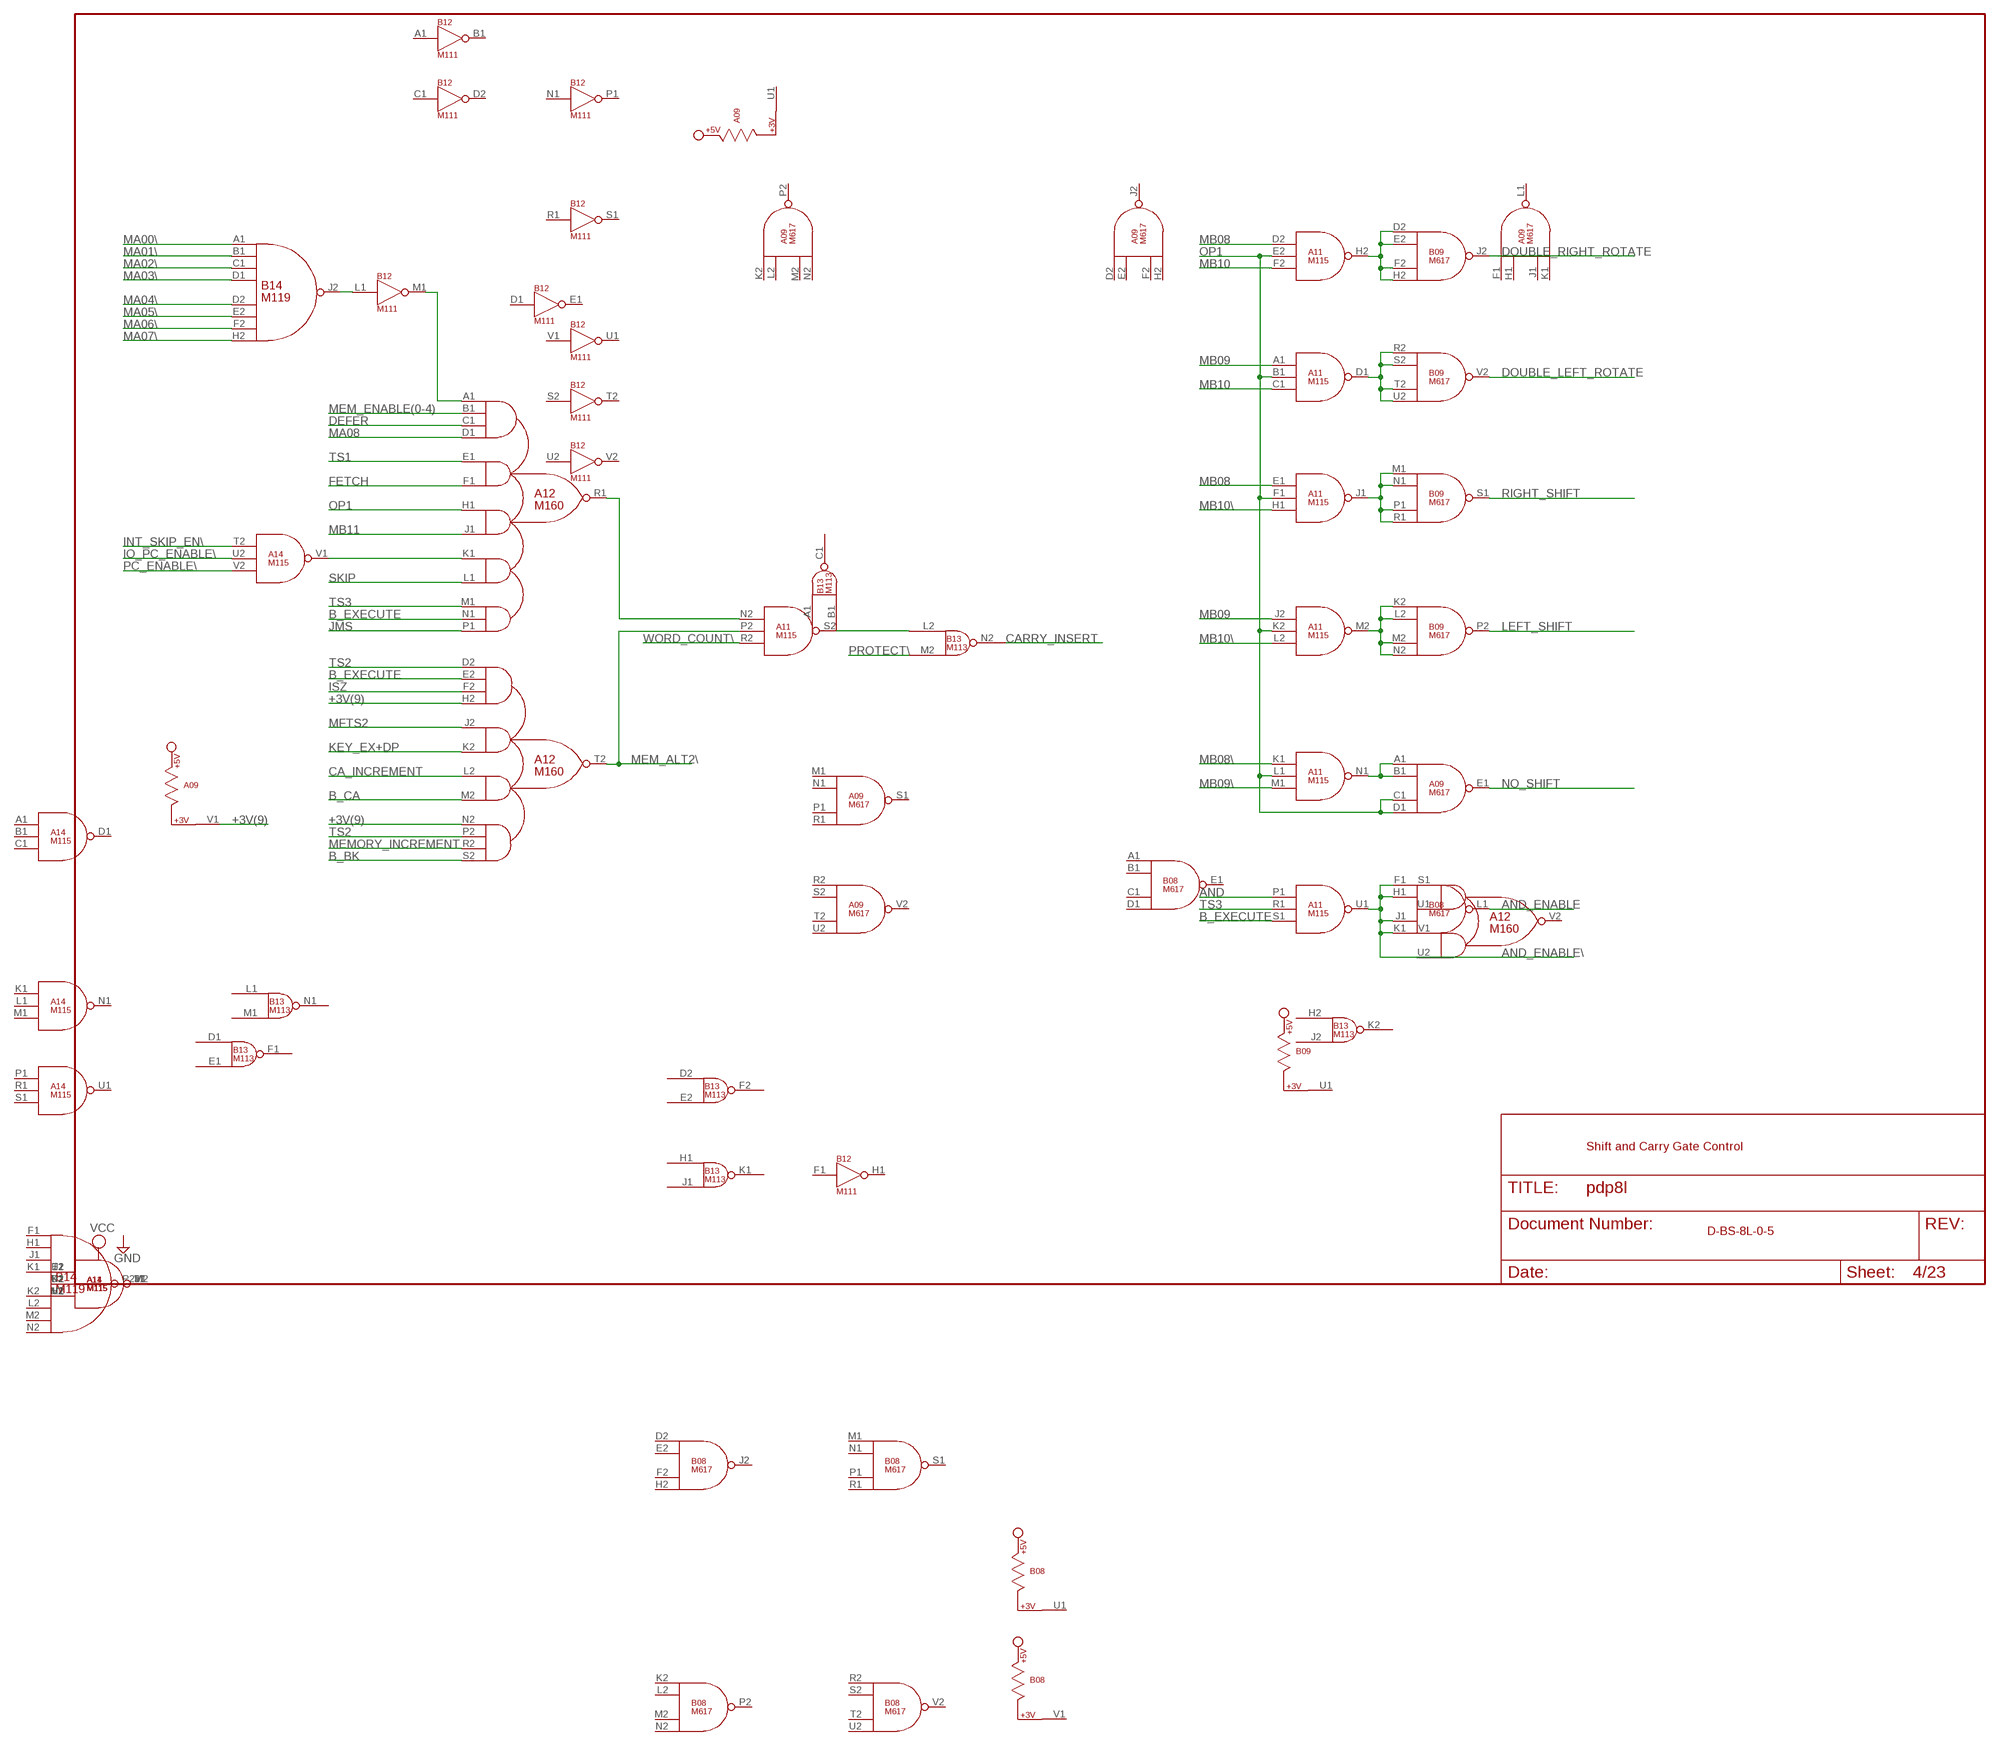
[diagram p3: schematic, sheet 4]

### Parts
A11  M115  [H807]
A14  M115  [H807]
B14  M119  [H807]

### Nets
+3V(9): A09.V1 A12.H2(T2:IN1D) A12.N2(T2:IN4A)
AND: A11.P1(U1:IN1) ; also sheet 2
AND_ENABLE: B08.L1(L1:OUT) ; also sheet 8,9,10,11
AND_ENABLE\: A11.U1(U1:OUT) B08.F1(L1:IN1) B08.H1(L1:IN2) B08.J1(L1:IN3) B08.K1(L1:IN4) ; also sheet 3
B_BK: A12.S2(T2:IN4D) ; also sheet 2,3
B_CA: A12.M2(T2:IN3B) ; also sheet 2,3
B_EXECUTE: A11.S1(U1:IN3) A12.E2(T2:IN1B) A12.N1(R1:IN5B) ; also sheet 2,3,5
CA_INCREMENT: A12.L2(T2:IN3A) ; also sheet 12
CARRY_INSERT: B13.N2(N2:OUT) ; also sheet 11
DEFER: A12.C1(R1:IN1C) ; also sheet 2,3,5,19
DOUBLE_LEFT_ROTATE: B09.V2(V2:OUT) ; also sheet 7,8,9,10,11
DOUBLE_RIGHT_ROTATE: B09.J2(J2:OUT) ; also sheet 7,8,9,10,11
FETCH: A12.F1(R1:IN2B) ; also sheet 2
INT_SKIP_EN\: A14.T2(V1:IN1) ; also sheet 3
IO_PC_ENABLE\: A14.U2(V1:IN2) ; also sheet 3
ISZ: A12.F2(T2:IN1C) ; also sheet 2,5
JMS: A12.P1(R1:IN5C) ; also sheet 2,3,5
KEY_EX+DP: A12.K2(T2:IN2B) ; also sheet 1,3
LEFT_SHIFT: B09.P2(P2:OUT) ; also sheet 7,8,9,10,11
MA00\: B14.A1(J2:IN1) ; also sheet 7,17,19
MA01\: B14.B1(J2:IN2) ; also sheet 7,19
MA02\: B14.C1(J2:IN3) ; also sheet 7,19
MA03\: B14.D1(J2:IN4) ; also sheet 7,17,19
MA04\: B14.D2(J2:IN5) ; also sheet 7,16,19
MA05\: B14.E2(J2:IN6) ; also sheet 7,16,19
MA06\: B14.F2(J2:IN7) ; also sheet 7,16,18,19
MA07\: B14.H2(J2:IN8) ; also sheet 7,16,19
MA08: A12.D1(R1:IN1D) ; also sheet 7,18
MB08: A11.D2(H2:IN1) A11.E1(J1:IN1) ; also sheet 5,7,12,13,22,23
MB08\: A11.K1(N1:IN1) ; also sheet 5,6,7,12,14,16,20,21,23
MB09: A11.A1(D1:IN1) A11.J2(M2:IN1) ; also sheet 1,3,7,12,23
MB09\: A11.M1(N1:IN3) ; also sheet 7,16,23
MB10: A11.C1(D1:IN3) A11.F2(H2:IN3) ; also sheet 1,7,12,23
MB10\: A11.H1(J1:IN3) A11.L2(M2:IN3) ; also sheet 6,7,16,23
MB11: A12.J1(R1:IN3B) ; also sheet 1,7,12,23
MEM_ALT2\: A11.P2(S2:IN2) A12.T2(T2:OUT) ; also sheet 2
MEM_ENABLE(0-4): A12.B1(R1:IN1B) ; also sheet 3,8,9
MEMORY_INCREMENT: A12.R2(T2:IN4C) ; also sheet 6,12
MFTS2: A12.J2(T2:IN2A) ; also sheet 1,3
N$54: B12.L1(M1:IN) B14.J2(J2:OUT)
N$57: A11.H2(H2:OUT) B09.D2(J2:IN1) B09.E2(J2:IN2) B09.F2(J2:IN3) B09.H2(J2:IN4)
N$58: A12.A1(R1:IN1A) B12.M1(M1:OUT)
N$59: A11.M2(M2:OUT) B09.K2(P2:IN1) B09.L2(P2:IN2) B09.M2(P2:IN3) B09.N2(P2:IN4)
N$60: A11.J1(J1:OUT) B09.M1(S1:IN1) B09.N1(S1:IN2) B09.P1(S1:IN3) B09.R1(S1:IN4)
N$61: A11.D1(D1:OUT) B09.R2(V2:IN1) B09.S2(V2:IN2) B09.T2(V2:IN3) B09.U2(V2:IN4)
N$62: A09.A1(E1:IN1) A09.B1(E1:IN2) A11.N1(N1:OUT)
N$65: A11.S2(S2:OUT) B13.L2(N2:IN1)
N$66: A11.N2(S2:IN1) A12.R1(R1:OUT)
N$73: A12.K1(R1:IN4A) A14.V1(V1:OUT)
NO_SHIFT: A09.E1(E1:OUT) ; also sheet 7,8,9,10,11
OP1: A09.C1(E1:IN3) A09.D1(E1:IN4) A11.B1(D1:IN2) A11.E2(H2:IN2) A11.F1(J1:IN2) A11.K2(M2:IN2) A11.L1(N1:IN2) A12.H1(R1:IN3A) ; also sheet 2,3
PC_ENABLE\: A14.V2(V1:IN3) ; also sheet 3
PROTECT\: B13.M2(N2:IN2) ; also sheet 2,3
RIGHT_SHIFT: B09.S1(S1:OUT) ; also sheet 7,8,9,10,11
SKIP: A12.L1(R1:IN4B) ; also sheet 5
TS1: A12.E1(R1:IN2A) ; also sheet 1,3
TS2: A12.D2(T2:IN1A) A12.P2(T2:IN4B) ; also sheet 1,2,3,5
TS3: A11.R1(U1:IN2) A12.M1(R1:IN5A) ; also sheet 1,2,3
WORD_COUNT\: A11.R2(S2:IN3) ; also sheet 2,6,19
Unconnected: B14.V1

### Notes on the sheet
- Shift and Carry Gate Control
- D-BS-8L-0-5

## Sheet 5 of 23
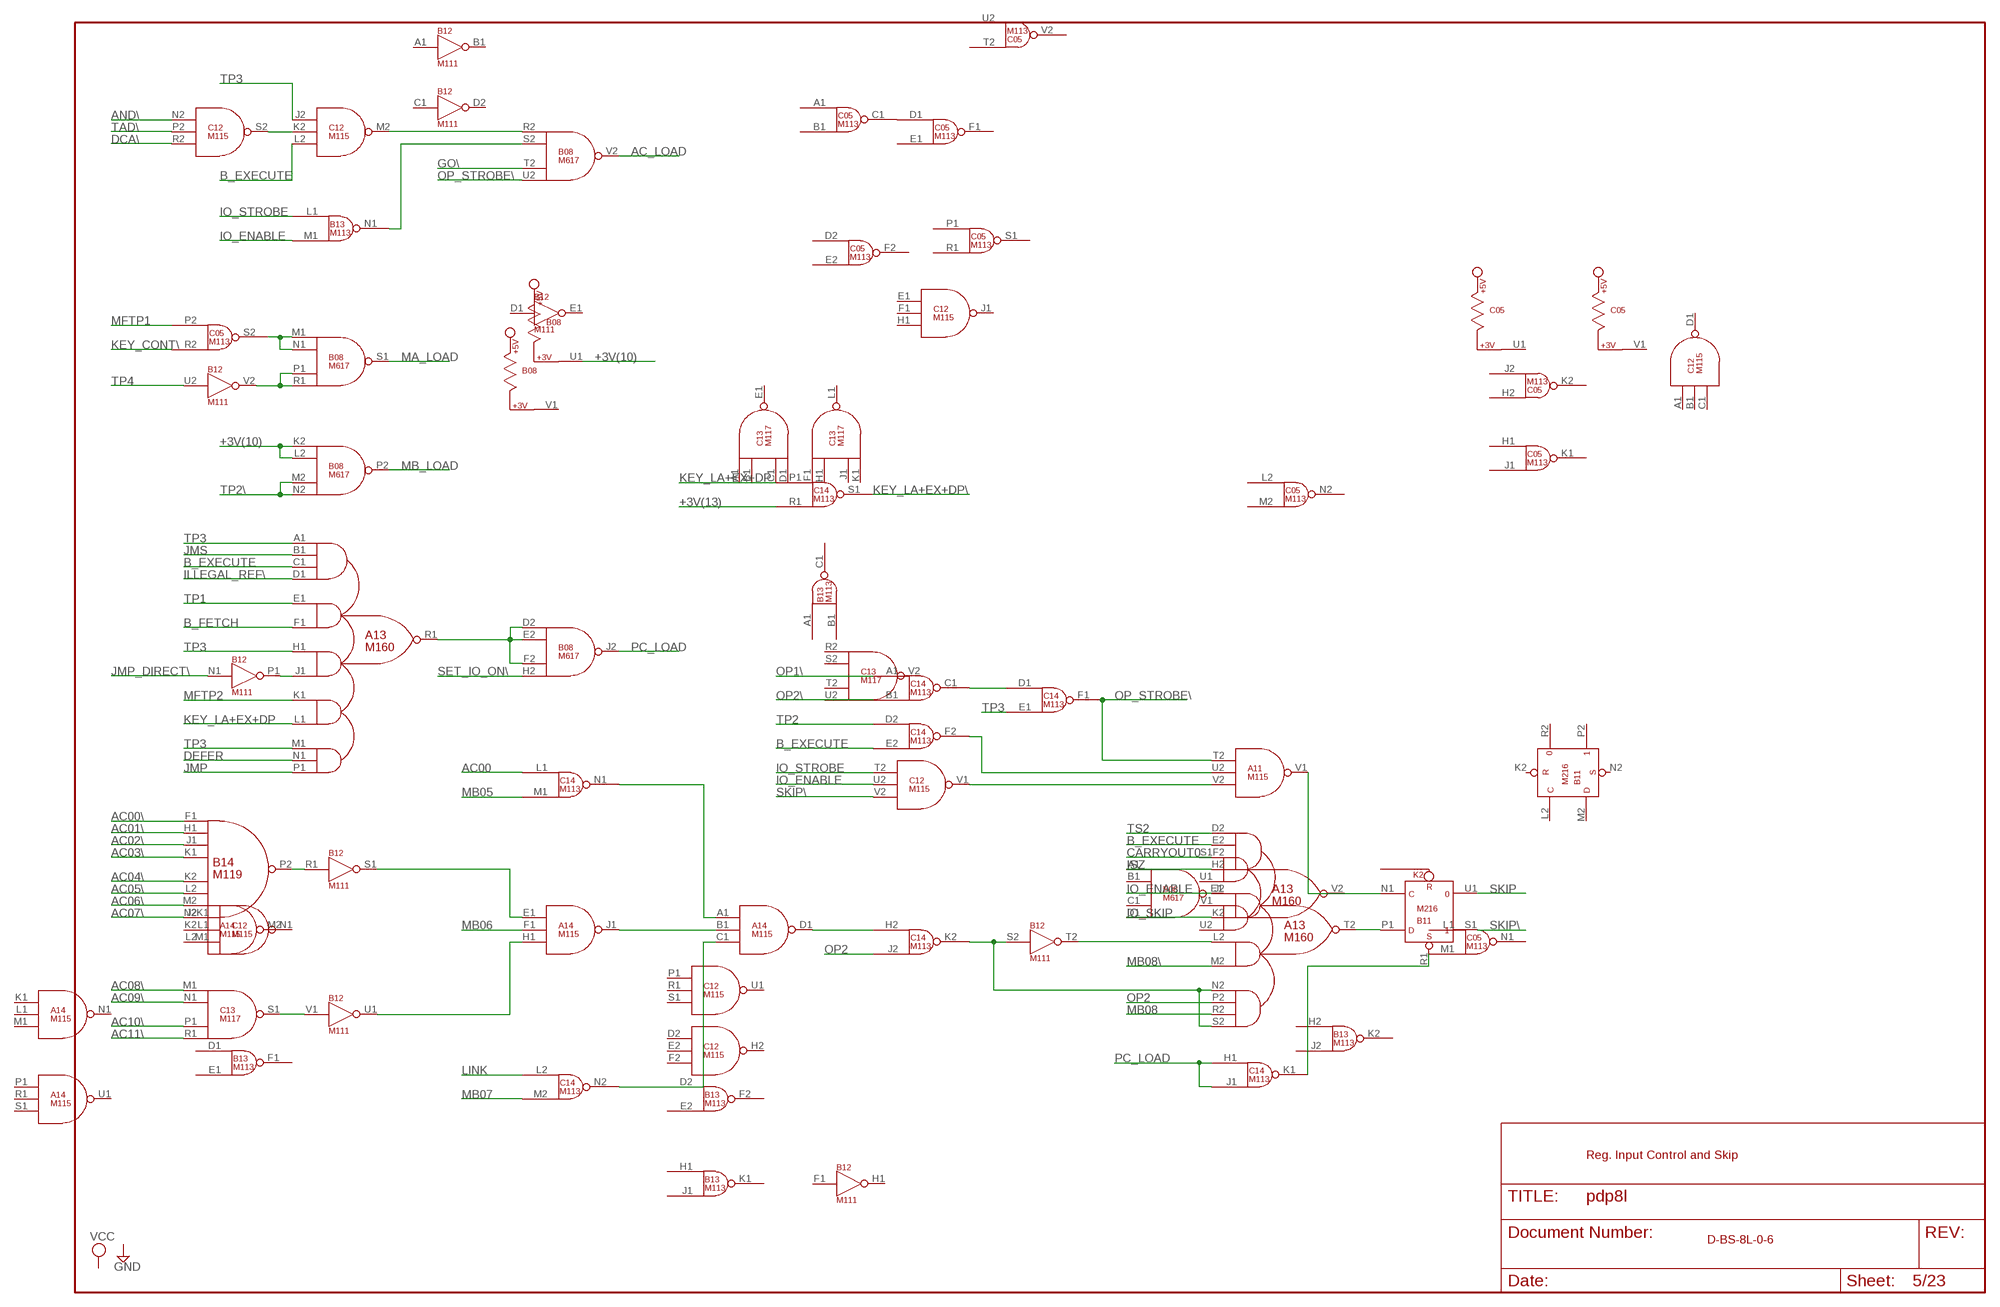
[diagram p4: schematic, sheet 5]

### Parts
C14  M113  [H807]

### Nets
+3V(10): B08.K2(P2:IN1) B08.L2(P2:IN2) B08.U1
+3V(13): C14.R1(S1:IN2) ; also sheet 15
AC00: C14.L1(N1:IN1) ; also sheet 7,12
AC00\: B14.F1(P2:IN1) ; also sheet 7
AC01\: B14.H1(P2:IN2) ; also sheet 7
AC02\: B14.J1(P2:IN3) ; also sheet 7
AC03\: B14.K1(P2:IN4) ; also sheet 7
AC04\: B14.K2(P2:IN5) ; also sheet 7
AC05\: B14.L2(P2:IN6) ; also sheet 7
AC06\: B14.M2(P2:IN7) ; also sheet 7
AC07\: B14.N2(P2:IN8) ; also sheet 7
AC08\: C13.M1(S1:IN1) ; also sheet 7
AC09\: C13.N1(S1:IN2) ; also sheet 7
AC10\: C13.P1(S1:IN3) ; also sheet 7
AC11\: C13.R1(S1:IN4) ; also sheet 7
AC_LOAD: B08.V2(V2:OUT) ; also sheet 7
AND\: C12.N2(S2:IN1) ; also sheet 2
B_EXECUTE: A13.C1(R1:IN1C) A13.E2(T2:IN1B) C12.L2(M2:IN3) C14.E2(F2:IN2) ; also sheet 2,3,4
B_FETCH: A13.F1(R1:IN2B) ; also sheet 2,3,6
CARRYOUT0: A13.F2(T2:IN1C) ; also sheet 6,7
DCA\: C12.R2(S2:IN3) ; also sheet 2
DEFER: A13.N1(R1:IN5B) ; also sheet 2,3,4,19
GO\: B08.T2(V2:IN3) ; also sheet 2,6
ILLEGAL_REF\: A13.D1(R1:IN1D) ; also sheet 1,2
IO_ENABLE: A13.J2(T2:IN2A) B13.M1(N1:IN2) C12.U2(V1:IN2) ; also sheet 3,8,9,10,11
IO_SKIP: A13.K2(T2:IN2B) ; also sheet 12
IO_STROBE: B13.L1(N1:IN1) C12.T2(V1:IN1) ; also sheet 1
ISZ: A13.H2(T2:IN1D) ; also sheet 2,4
JMP: A13.P1(R1:IN5C) ; also sheet 2,3
JMP_DIRECT\: B12.N1(P1:IN) ; also sheet 3
JMS: A13.B1(R1:IN1B) ; also sheet 2,3,4
KEY_CONT\: C05.R2(S2:IN2) ; also sheet 1
KEY_LA+EX+DP: A13.L1(R1:IN4B) C14.P1(S1:IN1) ; also sheet 1
KEY_LA+EX+DP\: C14.S1(S1:OUT) ; also sheet 6
LINK: C14.L2(N2:IN1) ; also sheet 7
MA_LOAD: B08.S1(S1:OUT) ; also sheet 7
MB05: C14.M1(N1:IN2) ; also sheet 3,7,12,20,23
MB06: A14.F1(J1:IN2) ; also sheet 3,7,12,14,23
MB07: C14.M2(N2:IN2) ; also sheet 3,7,12,13,21,23
MB08: A13.R2(T2:IN4C) ; also sheet 4,7,12,13,22,23
MB08\: A13.M2(T2:IN3B) ; also sheet 4,6,7,12,14,16,20,21,23
MB_LOAD: B08.P2(P2:OUT) ; also sheet 7
MFTP1: C05.P2(S2:IN1) ; also sheet 1,19
MFTP2: A13.K1(R1:IN4A) ; also sheet 1,2
N$67: C12.K2(M2:IN2) C12.S2(S2:OUT)
N$68: B08.P1(S1:IN3) B08.R1(S1:IN4) B12.V2(V2:OUT)
N$69: B08.M1(S1:IN1) B08.N1(S1:IN2) C05.S2(S2:OUT)
N$70: B08.R2(V2:IN1) C12.M2(M2:OUT)
N$71: B08.S2(V2:IN2) B13.N1(N1:OUT)
N$72: A13.J1(R1:IN3B) B12.P1(P1:OUT)
N$74: A13.R1(R1:OUT) B08.D2(J2:IN1) B08.E2(J2:IN2) B08.F2(J2:IN3)
N$75: B12.R1(S1:IN) B14.P2(P2:OUT)
N$76: B12.V1(U1:IN) C13.S1(S1:OUT)
N$77: A14.E1(J1:IN1) B12.S1(S1:OUT)
N$78: A14.H1(J1:IN3) B12.U1(U1:OUT)
N$79: A14.B1(D1:IN2) A14.J1(J1:OUT)
N$80: A14.C1(D1:IN3) C14.N2(N2:OUT)
N$81: A14.A1(D1:IN1) C14.N1(N1:OUT)
N$82: A14.D1(D1:OUT) C14.H2(K2:IN1)
N$83: A13.N2(T2:IN4A) A13.S2(T2:IN4D) B12.S2(T2:IN) C14.K2(K2:OUT)
N$84: A13.L2(T2:IN3A) B12.T2(T2:OUT)
N$85: B11.R1(S1:S) C14.K1(K1:OUT)
N$86: A11.V1(V1:OUT) B11.N1(S1:C)
N$87: A13.T2(T2:OUT) B11.P1(S1:D)
N$88: C14.C1(C1:OUT) C14.D1(F1:IN1)
N$89: A11.U2(V1:IN2) C14.F2(F2:OUT)
N$90: A11.V2(V1:IN3) C12.V1(V1:OUT)
OP1\: C14.A1(C1:IN1) ; also sheet 2
OP2: A13.P2(T2:IN4B) C14.J2(K2:IN2) ; also sheet 1,2,3
OP2\: C14.B1(C1:IN2) ; also sheet 2
OP_STROBE\: A11.T2(V1:IN1) B08.U2(V2:IN4) C14.F1(F1:OUT)
PC_LOAD: B08.J2(J2:OUT) C14.H1(K1:IN1) C14.J1(K1:IN2) ; also sheet 7
SET_IO_ON\: B08.H2(J2:IN4) ; also sheet 1
SKIP: B11.U1 ; also sheet 4
SKIP\: B11.S1 C12.V2(V1:IN3)
TAD\: C12.P2(S2:IN2) ; also sheet 2
TP1: A13.E1(R1:IN2A) ; also sheet 1,2,6
TP2: C14.D2(F2:IN1) ; also sheet 1,2,6
TP2\: B08.M2(P2:IN3) B08.N2(P2:IN4) ; also sheet 1
TP3: A13.A1(R1:IN1A) A13.H1(R1:IN3A) A13.M1(R1:IN5A) C12.J2(M2:IN1) C14.E1(F1:IN2) ; also sheet 1,23
TP4: B12.U2(V2:IN) ; also sheet 1,2,6
TS2: A13.D2(T2:IN1A) ; also sheet 1,2,3,4
Unconnected: C14.U1 C14.V1

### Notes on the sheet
- Reg. Input Control and Skip
- D-BS-8L-0-6

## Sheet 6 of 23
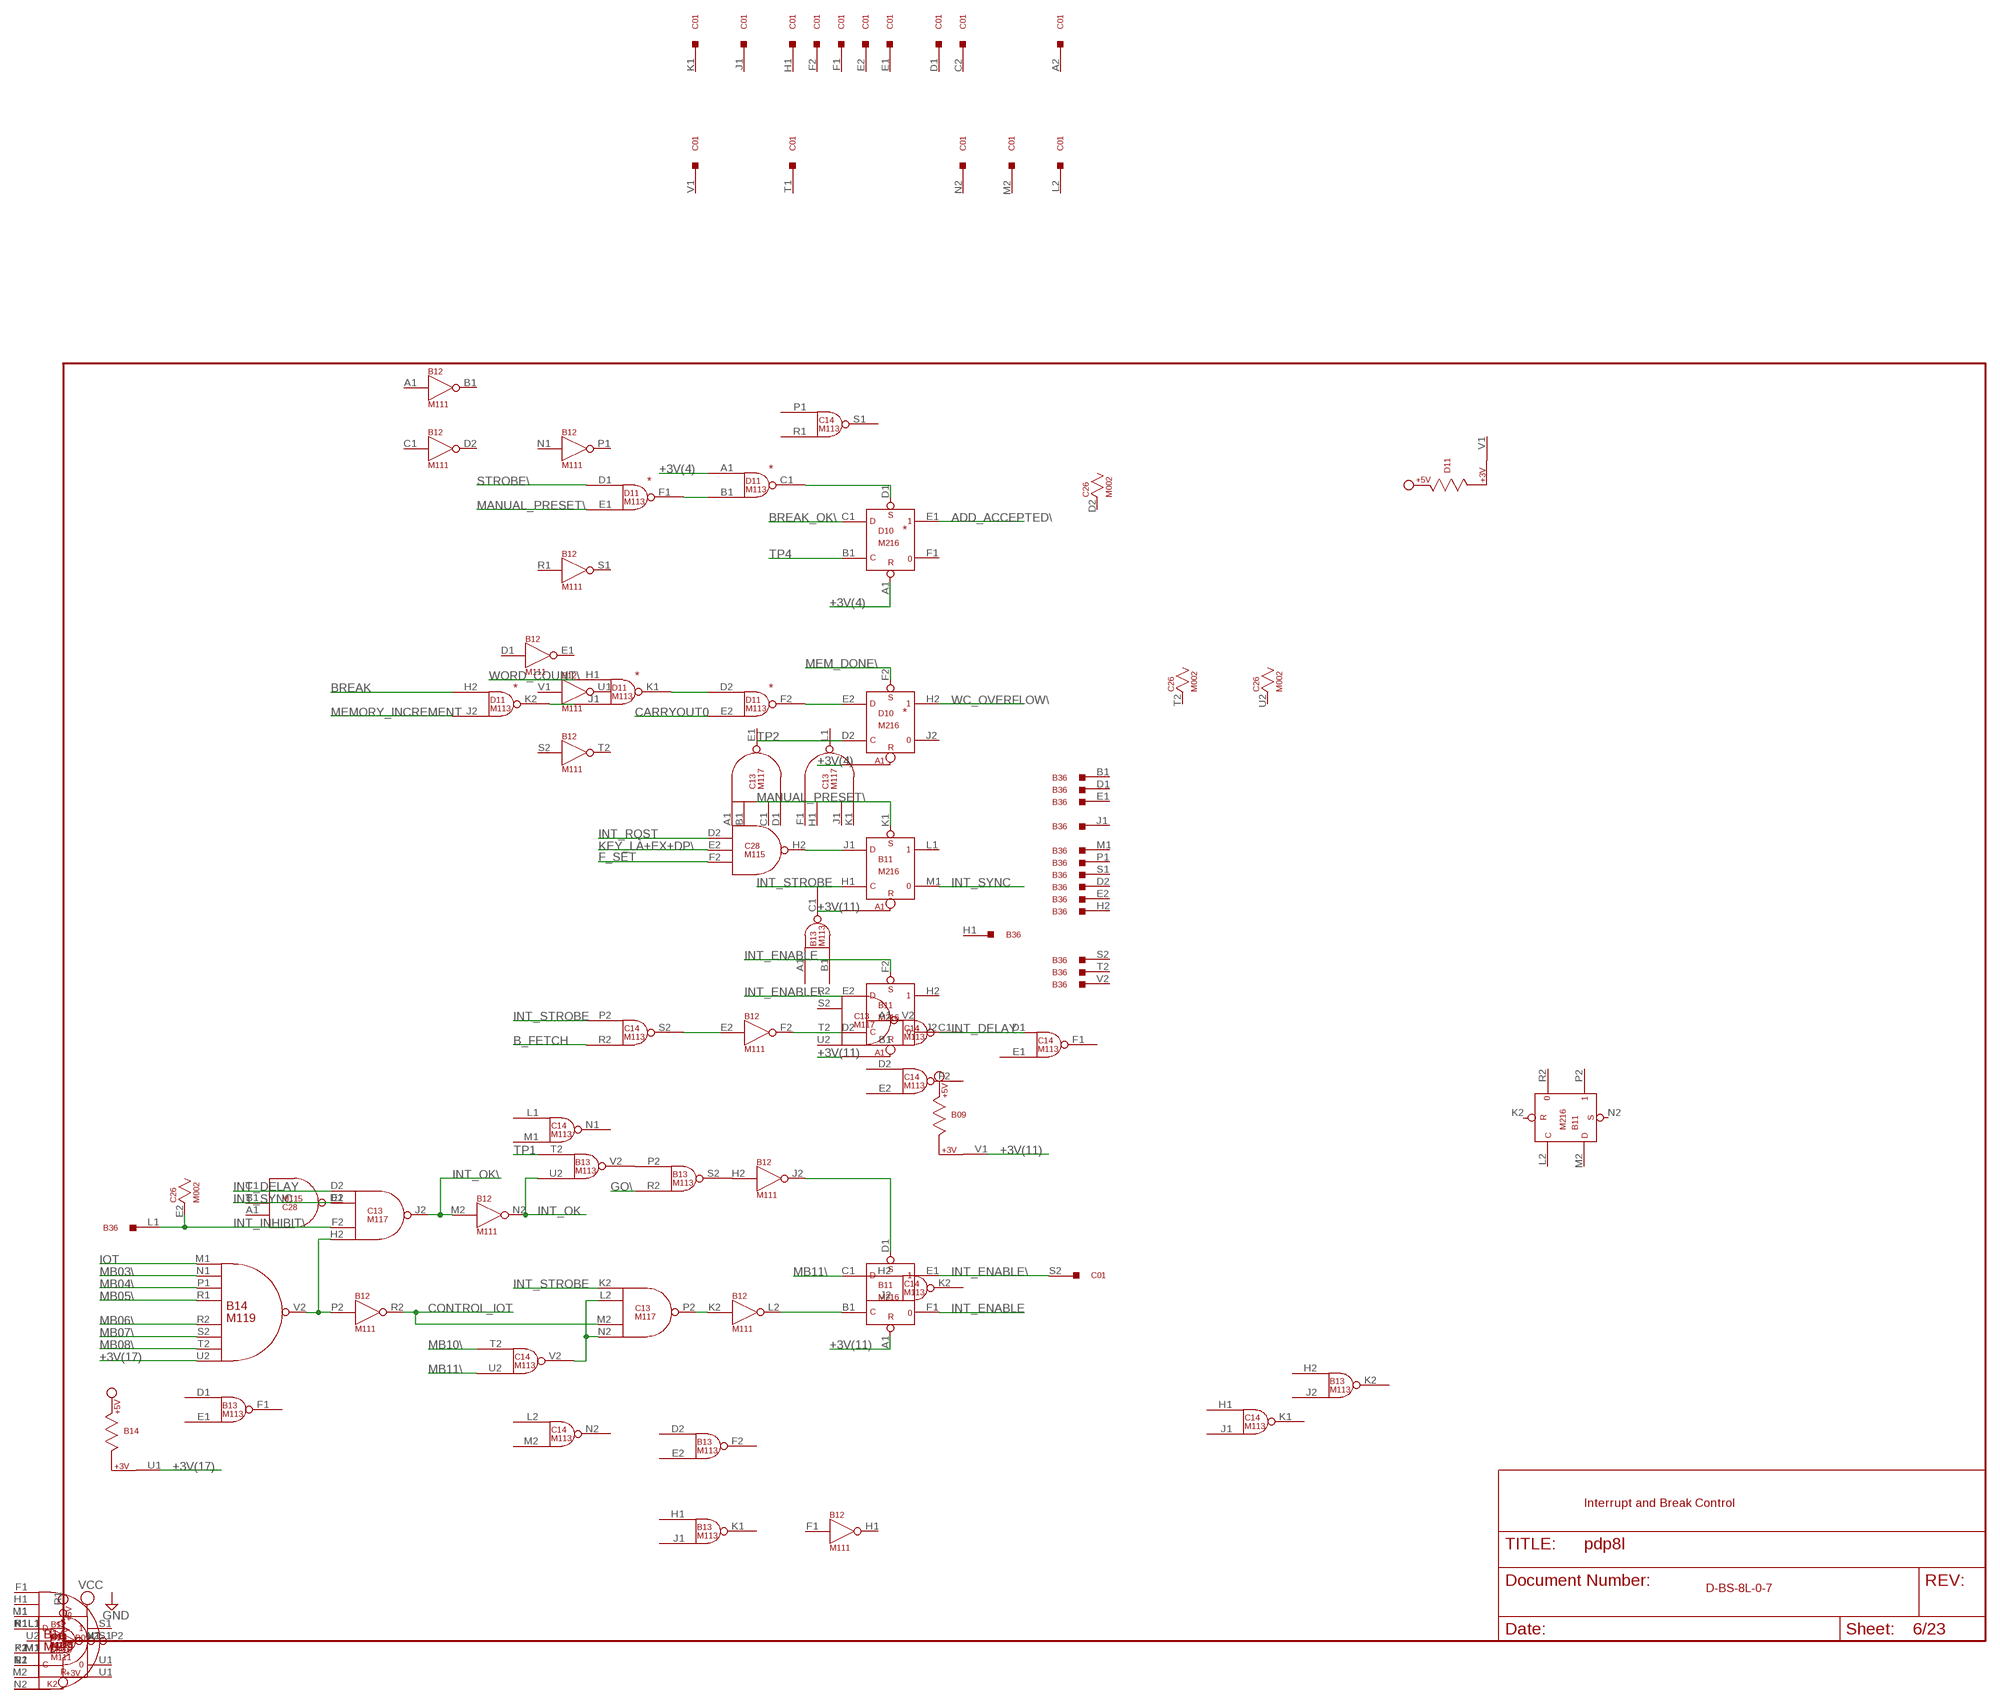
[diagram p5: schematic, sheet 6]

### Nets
+3V(4): D10.A1(E1:R) D11.A1(C1:IN1) ; also sheet 2
+3V(11): B09.V1 B11.A1(E1:R) ; also sheet 7
+3V(17): B14.U1 B14.U2(V2:IN8)
ADD_ACCEPTED\: D10.E1 ; also sheet 12
B_FETCH: C14.R2(S2:IN2) ; also sheet 2,3,5
BREAK: D11.H2(K2:IN1) ; also sheet 2
BREAK_OK\: D10.C1(E1:D) ; also sheet 2
CARRYOUT0: D11.E2(F2:IN2) ; also sheet 5,7
CONTROL_IOT: B12.R2(R2:OUT) C13.M2(P2:IN3)
F_SET: C28.F2(H2:IN3) ; also sheet 1,2,3
GO\: B13.R2(S2:IN2) ; also sheet 2,5
INT_DELAY: B11.J2 C13.D2(J2:IN1)
INT_ENABLE: B11.F1 B11.F2(H2:S)
INT_ENABLE\: B11.E1 B11.E2(H2:D) C01.S2
INT_INHIBIT\: B36.L1 C13.F2(J2:IN3) C26.E2
INT_OK: B12.N2(N2:OUT) B13.U2(V2:IN2) ; also sheet 2,19
INT_OK\: B12.M2(N2:IN) C13.J2(J2:OUT) ; also sheet 2,3
INT_RQST: C28.D2(H2:IN1) ; also sheet 12
INT_STROBE: B11.H1(L1:C) C13.K2(P2:IN1) C14.P2(S2:IN1) ; also sheet 1
INT_SYNC: B11.M1 C13.E2(J2:IN2)
IOT: B14.M1(V2:IN1) ; also sheet 1,2
KEY_LA+EX+DP\: C28.E2(H2:IN2) ; also sheet 5
MANUAL_PRESET\: B11.K1(L1:S) D11.E1(F1:IN2) ; also sheet 1,2
MB03\: B14.N1(V2:IN2) ; also sheet 2,3,7,12,13,14,16,20,21,22,23
MB04\: B14.P1(V2:IN3) ; also sheet 3,7,12,13,14,20,21,22,23
MB05\: B14.R1(V2:IN4) ; also sheet 3,7,12,13,14,21,22,23
MB06\: B14.R2(V2:IN5) ; also sheet 3,7,12,13,20,21,22,23
MB07\: B14.S2(V2:IN6) ; also sheet 3,7,12,14,20,22,23
MB08\: B14.T2(V2:IN7) ; also sheet 4,5,7,12,14,16,20,21,23
MB10\: C14.T2(V2:IN1) ; also sheet 4,7,16,23
MB11\: B11.C1(E1:D) C14.U2(V2:IN2) ; also sheet 1,2,3,7,16,23
MEM_DONE\: D10.F2(H2:S) ; also sheet 1,15
MEMORY_INCREMENT: D11.J2(K2:IN2) ; also sheet 4,12
N$91: B12.P2(R2:IN) B14.V2(V2:OUT) C13.H2(J2:IN4)
N$92: C13.L2(P2:IN2) C13.N2(P2:IN4) C14.V2(V2:OUT)
N$93: B12.K2(L2:IN) C13.P2(P2:OUT)
N$94: B13.P2(S2:IN1) B13.V2(V2:OUT)
N$95: B12.H2(J2:IN) B13.S2(S2:OUT)
N$96: B11.B1(E1:C) B12.L2(L2:OUT)
N$97: B11.D1(E1:S) B12.J2(J2:OUT)
N$98: B11.J1(L1:D) C28.H2(H2:OUT)
N$99: D11.J1(K1:IN2) D11.K2(K2:OUT)
N$100: B11.D2(H2:C) B12.F2(F2:OUT)
N$101: B12.E2(F2:IN) C14.S2(S2:OUT)
N$102: D10.E2(H2:D) D11.F2(F2:OUT)
N$103: D11.D2(F2:IN1) D11.K1(K1:OUT)
N$104: D11.B1(C1:IN2) D11.F1(F1:OUT)
N$105: D10.D1(E1:S) D11.C1(C1:OUT)
STROBE\: D11.D1(F1:IN1) ; also sheet 1,15
TP1: B13.T2(V2:IN1) ; also sheet 1,2,5
TP2: D10.D2(H2:C) ; also sheet 1,2,5
TP4: D10.B1(E1:C) ; also sheet 1,2,5
WC_OVERFLOW\: D10.H2 ; also sheet 12
WORD_COUNT\: D11.H1(K1:IN1) ; also sheet 2,4,19
Unconnected: B11.H2 B11.L1 D10.F1 D10.J2

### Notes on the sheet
- *
- *
- *
- *
- * | *
- *
- Interrupt and Break Control
- D-BS-8L-0-7

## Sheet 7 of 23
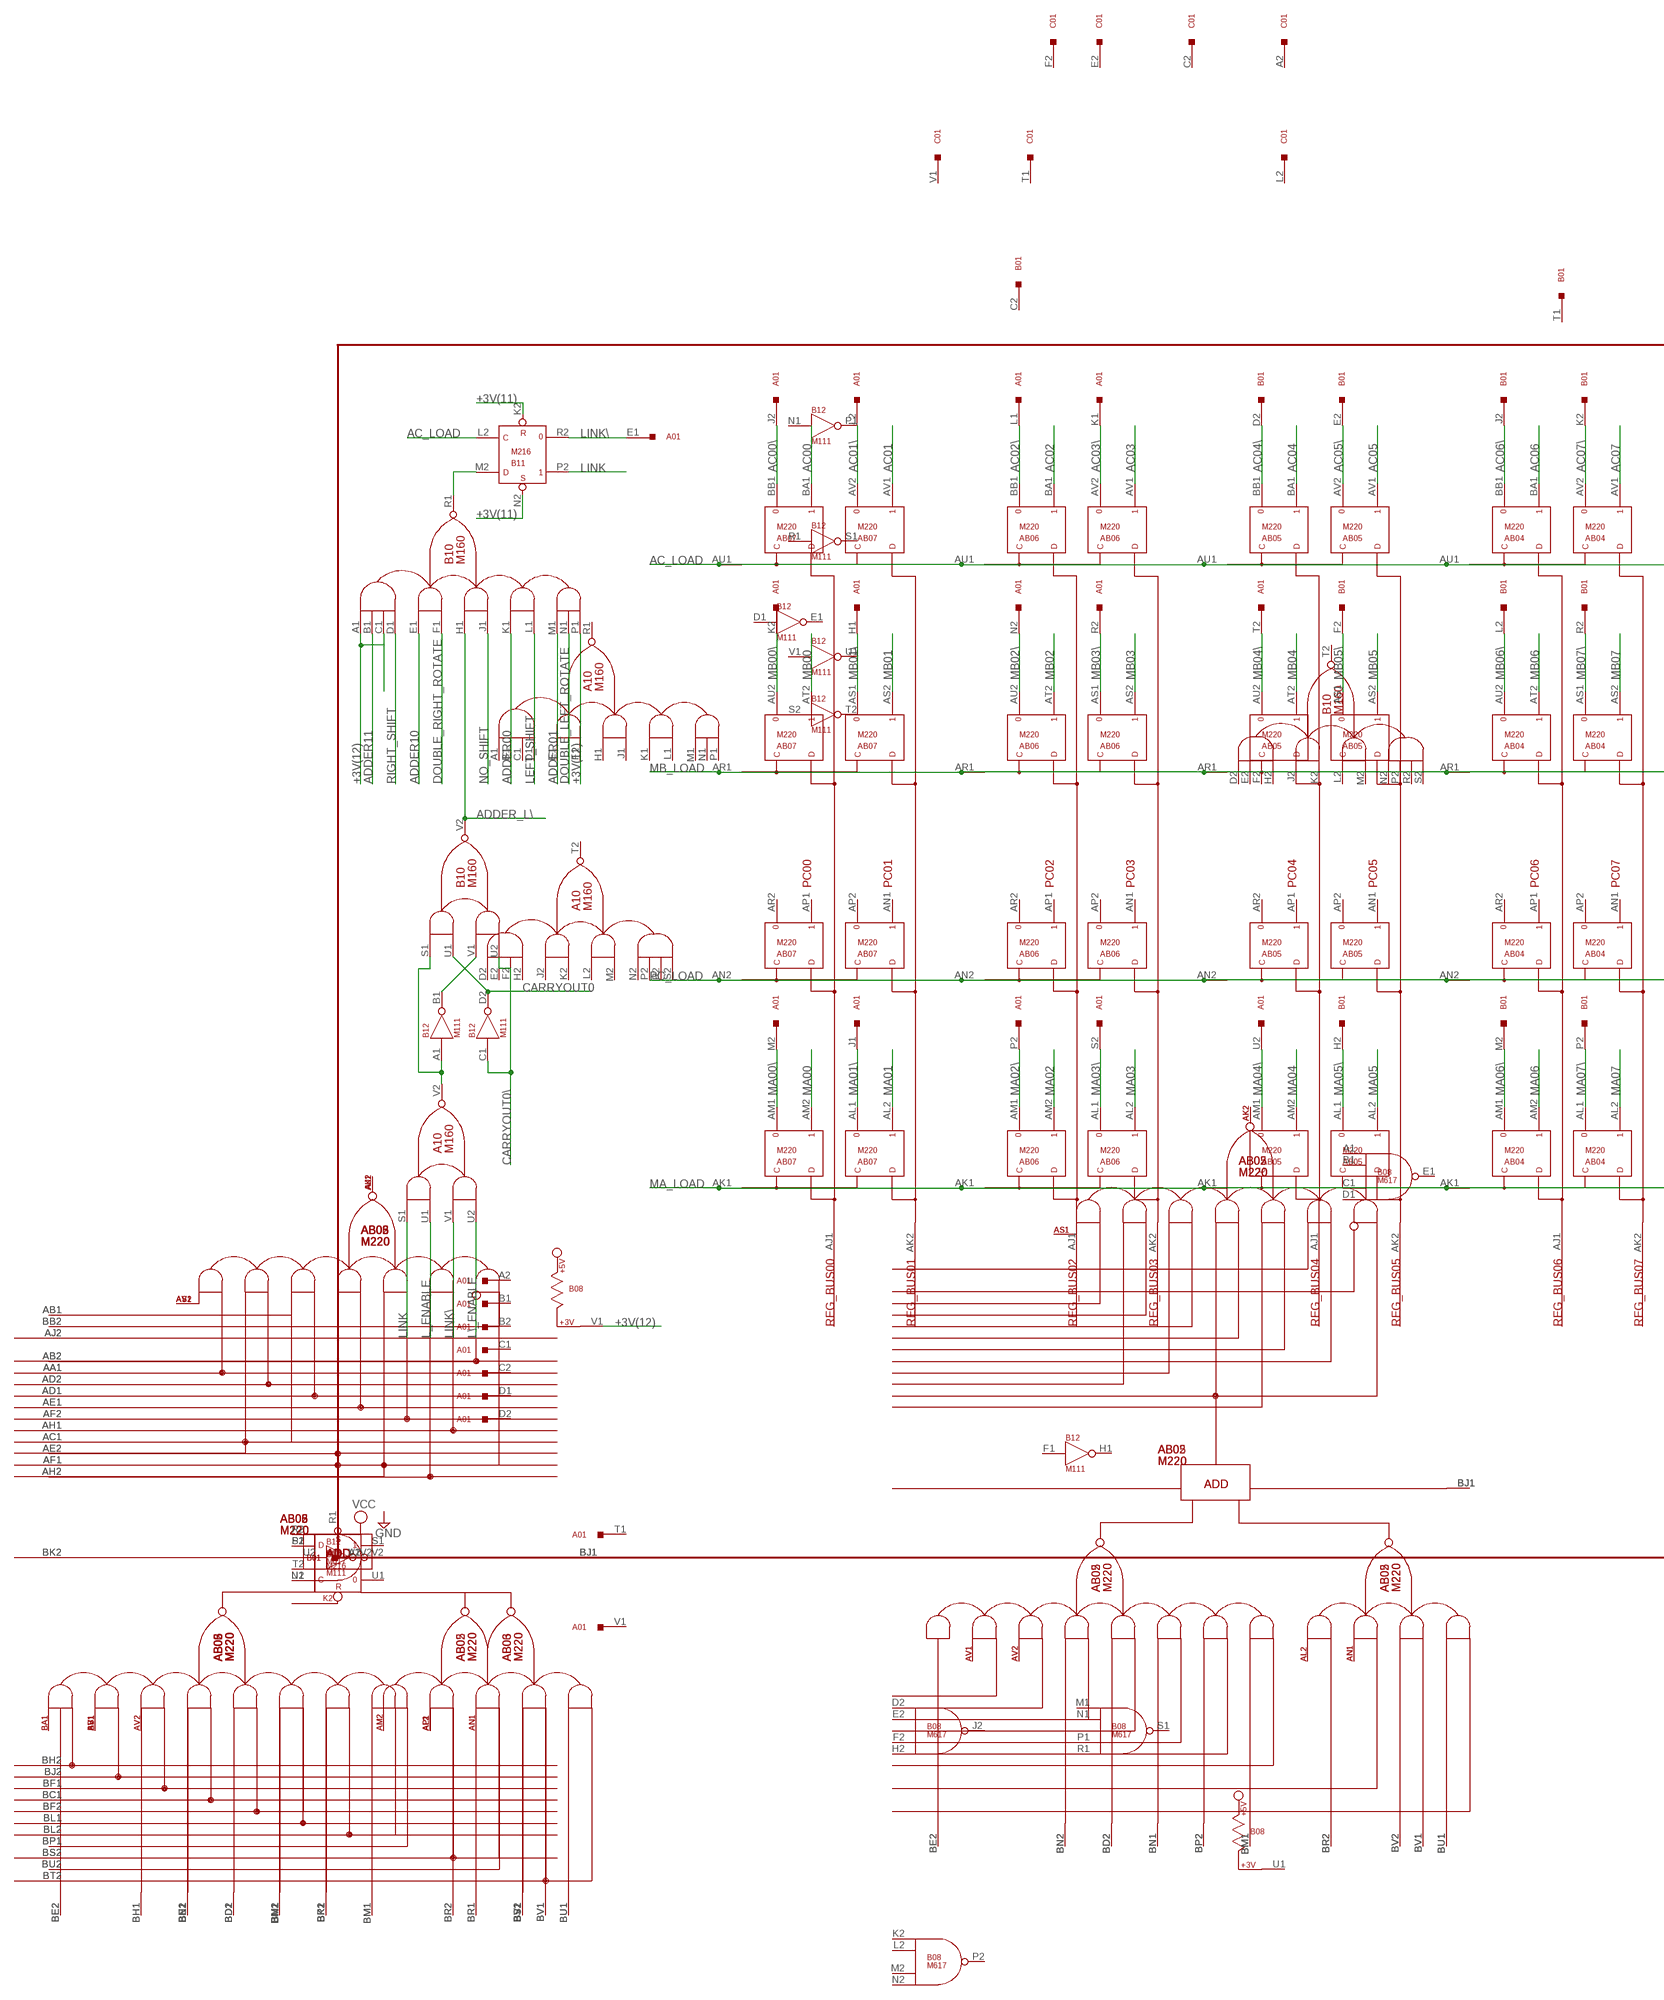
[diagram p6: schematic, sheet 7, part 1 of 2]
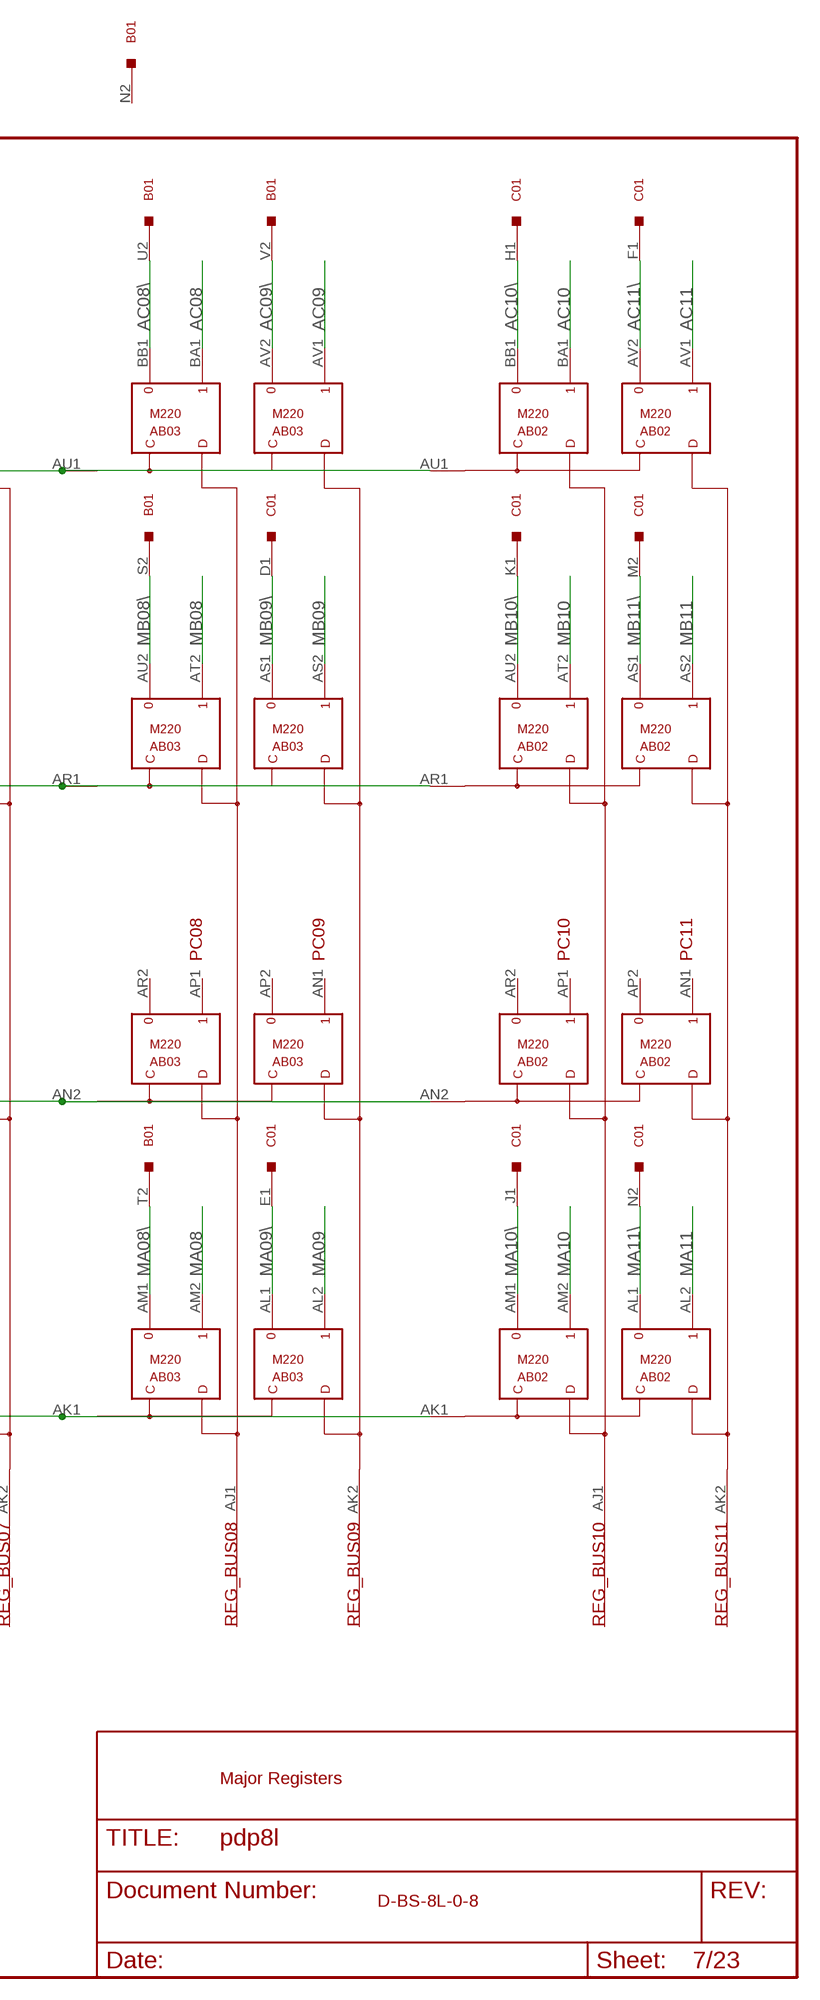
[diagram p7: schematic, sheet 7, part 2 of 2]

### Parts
AB02  M220  M220X  [H807-2]
AB03  M220  M220X  [H807-2]
AB04  M220  M220X  [H807-2]
AB05  M220  M220X  [H807-2]
AB06  M220  M220X  [H807-2]
AB07  M220  M220X  [H807-2]
B01  G921  M916  [H807]

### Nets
+3V(11): B11.K2(P2:R) B11.N2(P2:S) ; also sheet 6
+3V(12): B08.V1 B10.A1(R1:IN1A) B10.C1(R1:IN1C) B10.P1(R1:IN5C)
AC00: AB07.BA1 ; also sheet 5,12
AC00\: A01.J2 AB07.BB1 ; also sheet 5
AC01: AB07.AV1 ; also sheet 12
AC01\: A01.L2 AB07.AV2 ; also sheet 5
AC02: AB06.BA1 ; also sheet 12
AC02\: A01.L1 AB06.BB1 ; also sheet 5
AC03: AB06.AV1 ; also sheet 12
AC03\: A01.K1 AB06.AV2 ; also sheet 5
AC04: AB05.BA1 ; also sheet 12,14,21
AC04\: AB05.BB1 B01.D2 ; also sheet 5
AC05: AB05.AV1 ; also sheet 12,14,21
AC05\: AB05.AV2 B01.E2 ; also sheet 5
AC06: AB04.BA1 ; also sheet 12,14,21
AC06\: AB04.BB1 B01.J2 ; also sheet 5
AC07: AB04.AV1 ; also sheet 12,14,21
AC07\: AB04.AV2 B01.K2 ; also sheet 5
AC08: AB03.BA1 ; also sheet 12,14,21
AC08\: AB03.BB1 B01.U2 ; also sheet 5
AC09: AB03.AV1 ; also sheet 12,14,21
AC09\: AB03.AV2 B01.V2 ; also sheet 5
AC10: AB02.BA1 ; also sheet 12,14,21
AC10\: AB02.BB1 C01.H1 ; also sheet 5
AC11: AB02.AV1 ; also sheet 12,14,21
AC11\: AB02.AV2 C01.F1 ; also sheet 5
AC_LOAD: AB02.AU1 AB03.AU1 AB04.AU1 AB05.AU1 AB06.AU1 AB07.AU1 B11.L2(P2:C) ; also sheet 5
ADDER00: B10.K1(R1:IN4A) ; also sheet 8,11
ADDER01: B10.M1(R1:IN5A) ; also sheet 8
ADDER10: B10.E1(R1:IN2A) ; also sheet 10,11
ADDER11: B10.B1(R1:IN1B) ; also sheet 8,10,11
ADDER_L\: B10.H1(R1:IN3A) B10.V2(V2:OUT) ; also sheet 8,11
CARRYOUT0: B10.U1(V2:IN1B) B12.D2(D2:OUT) ; also sheet 5,6
CARRYOUT0\: B10.U2(V2:IN2B) B12.C1(D2:IN) ; also sheet 8
DOUBLE_LEFT_ROTATE: B10.N1(R1:IN5B) ; also sheet 4,8,9,10,11
DOUBLE_RIGHT_ROTATE: B10.F1(R1:IN2B) ; also sheet 4,8,9,10,11
L\_ENABLE: A10.U2(V2:IN2B) ; also sheet 3
L_ENABLE: A10.U1(V2:IN1B) ; also sheet 3
LEFT_SHIFT: B10.L1(R1:IN4B) ; also sheet 4,8,9,10,11
LINK: A10.S1(V2:IN1A) B11.P2 ; also sheet 5
LINK\: A01.E1 A10.V1(V2:IN2A) B11.R2
MA00: AB07.AM2 ; also sheet 2,17
MA00\: A01.M2 AB07.AM1 ; also sheet 4,17,19
MA01: AB07.AL2 ; also sheet 2,17
MA01\: A01.J1 AB07.AL1 ; also sheet 4,19
MA02: AB06.AM2 ; also sheet 2,17
MA02\: A01.P2 AB06.AM1 ; also sheet 4,19
MA03: AB06.AL2 ; also sheet 2,17
MA03\: A01.S2 AB06.AL1 ; also sheet 4,17,19
MA04: AB05.AM2 ; also sheet 2,17
MA04\: A01.U2 AB05.AM1 ; also sheet 4,16,19
MA05: AB05.AL2 ; also sheet 17
MA05\: AB05.AL1 B01.H2 ; also sheet 4,16,19
MA06: AB04.AM2 ; also sheet 18
MA06\: AB04.AM1 B01.M2 ; also sheet 4,16,18,19
MA07: AB04.AL2 ; also sheet 18
MA07\: AB04.AL1 B01.P2 ; also sheet 4,16,19
MA08: AB03.AM2 ; also sheet 4,18
MA08\: AB03.AM1 B01.T2 ; also sheet 19
MA09: AB03.AL2 ; also sheet 18
MA09\: AB03.AL1 C01.E1 ; also sheet 18,19
MA10: AB02.AM2 ; also sheet 18
MA10\: AB02.AM1 C01.J1 ; also sheet 19
MA11: AB02.AL2 ; also sheet 18
MA11\: AB02.AL1 C01.N2 ; also sheet 19
MA_LOAD: AB02.AK1 AB03.AK1 AB04.AK1 AB05.AK1 AB06.AK1 AB07.AK1 ; also sheet 5
MB00: AB07.AT2 ; also sheet 12,23
MB00\: A01.K2 AB07.AU2 ; also sheet 16,23
MB01: AB07.AS2 ; also sheet 12,23
MB01\: A01.H1 AB07.AS1 ; also sheet 16,23
MB02: AB06.AT2 ; also sheet 12,23
MB02\: A01.N2 AB06.AU2 ; also sheet 16,23
MB03: AB06.AS2 ; also sheet 2,12,23
MB03\: A01.R2 AB06.AS1 ; also sheet 2,3,6,12,13,14,16,20,21,22,23
MB04: AB05.AT2 ; also sheet 3,12,23
MB04\: A01.T2 AB05.AU2 ; also sheet 3,6,12,13,14,20,21,22,23
MB05: AB05.AS2 ; also sheet 3,5,12,20,23
MB05\: AB05.AS1 B01.F2 ; also sheet 3,6,12,13,14,21,22,23
MB06: AB04.AT2 ; also sheet 3,5,12,14,23
MB06\: AB04.AU2 B01.L2 ; also sheet 3,6,12,13,20,21,22,23
MB07: AB04.AS2 ; also sheet 3,5,12,13,21,23
MB07\: AB04.AS1 B01.R2 ; also sheet 3,6,12,14,20,22,23
MB08: AB03.AT2 ; also sheet 4,5,12,13,22,23
MB08\: AB03.AU2 B01.S2 ; also sheet 4,5,6,12,14,16,20,21,23
MB09: AB03.AS2 ; also sheet 1,3,4,12,23
MB09\: AB03.AS1 C01.D1 ; also sheet 4,16,23
MB10: AB02.AT2 ; also sheet 1,4,12,23
MB10\: AB02.AU2 C01.K1 ; also sheet 4,6,16,23
MB11: AB02.AS2 ; also sheet 1,4,12,23
MB11\: AB02.AS1 C01.M2 ; also sheet 1,2,3,6,16,23
MB_LOAD: AB02.AR1 AB03.AR1 AB04.AR1 AB05.AR1 AB06.AR1 AB07.AR1 ; also sheet 5
N$106: B10.R1(R1:OUT) B11.M2(P2:D)
N$116: A10.V2(V2:OUT) B10.S1(V2:IN1A) B12.A1(B1:IN)
N$123: B10.V1(V2:IN2A) B12.B1(B1:OUT)
NO_SHIFT: B10.J1(R1:IN3B) ; also sheet 4,8,9,10,11
PC_LOAD: AB02.AN2 AB03.AN2 AB04.AN2 AB05.AN2 AB06.AN2 AB07.AN2 ; also sheet 5
RIGHT_SHIFT: B10.D1(R1:IN1D) ; also sheet 4,8,9,10,11
Unconnected: B01.A1 B01.B1 B01.B2 B01.C1 B01.D1 B01.E1 B01.F1 B01.H1 B01.J1 B01.K1 B01.L1 B01.M1 B01.N1 B01.P1 B01.R1 B01.S1 B01.U1

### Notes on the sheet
- PC00 | PC01 | PC02 | PC03 | PC04 | PC05 | PC06 | PC07 | PC08 | PC09 | PC10 | PC11
- REG_BUS00 | REG_BUS01 | REG_BUS02 | REG_BUS03 | REG_BUS04 | REG_BUS05 | REG_BUS06 | REG_BUS07 | REG_BUS08 | REG_BUS09 | REG_BUS10 | REG_BUS11
- Major Registers
- D-BS-8L-0-8

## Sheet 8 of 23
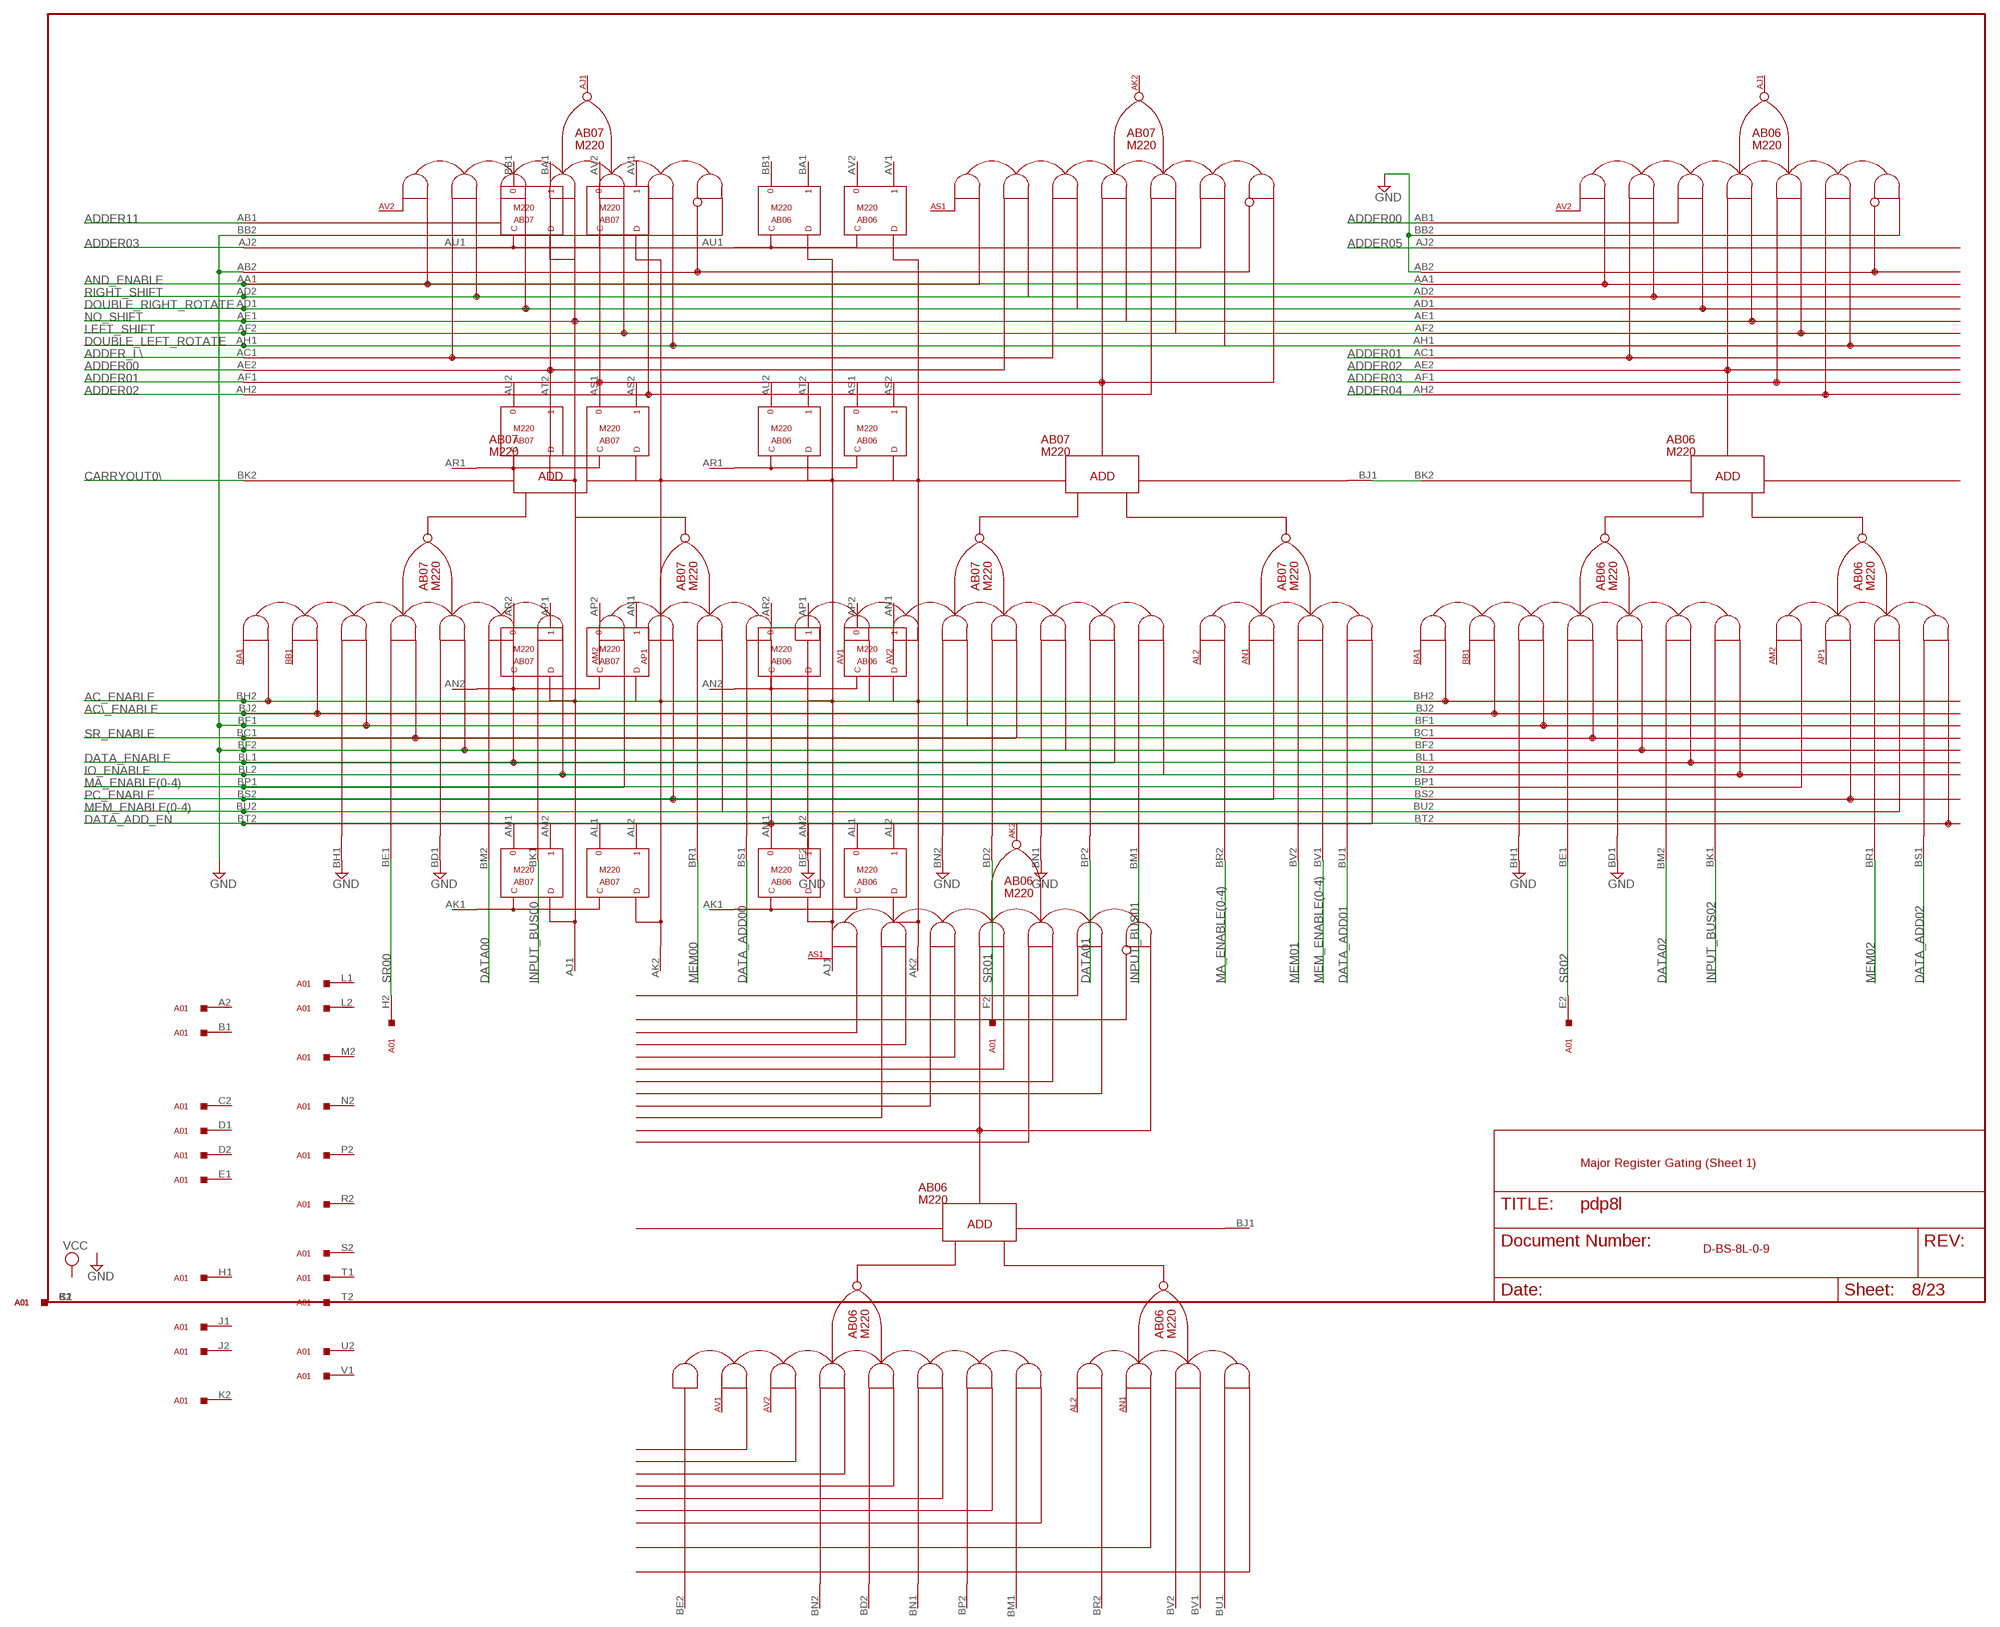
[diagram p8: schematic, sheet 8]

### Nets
AC\_ENABLE: AB06.BJ2(B0:BJ2) AB07.BJ2(B0:BJ2) ; also sheet 3,9,10,11
AC_ENABLE: AB06.BH2(B0:BH2) AB07.BH2(B0:BH2) ; also sheet 3,9,10,11
ADDER00: AB06.AB1(B0:AB1) AB07.AE2(B0:AE2) ; also sheet 7,11
ADDER01: AB06.AC1(B0:AC1) AB07.AF1(B0:AF1) ; also sheet 7
ADDER02: AB06.AE2(B0:AE2) AB07.AH2(B0:AH2) ; also sheet 9
ADDER03: AB06.AF1(B0:AF1) AB07.AJ2(B0:AJ2) ; also sheet 9
ADDER04: AB06.AH2(B0:AH2) ; also sheet 9,10
ADDER05: AB06.AJ2(B0:AJ2) ; also sheet 9,10
ADDER11: AB07.AB1(B0:AB1) ; also sheet 7,10,11
ADDER_L\: AB07.AC1(B0:AC1) ; also sheet 7,11
AND_ENABLE: AB06.AA1(B0:AA1) AB07.AA1(B0:AA1) ; also sheet 4,9,10,11
CARRYOUT0\: AB07.BK2(B0:BK2) ; also sheet 7
DATA00: AB07.BM2(B0:BM2) ; also sheet 12
DATA01: AB07.BP2(B1:BP2) ; also sheet 12
DATA02: AB06.BM2(B0:BM2) ; also sheet 12
DATA_ADD00: AB07.BS1(B0:BS1) ; also sheet 12
DATA_ADD01: AB07.BU1(B1:BU1) ; also sheet 12
DATA_ADD02: AB06.BS1(B0:BS1) ; also sheet 12
DATA_ADD_EN: AB06.BT2(B0:BT2) AB07.BT2(B0:BT2) ; also sheet 3,9,10,11
DATA_ENABLE: AB06.BL1(B0:BL1) AB07.BL1(B0:BL1) ; also sheet 3,9,10,11
DOUBLE_LEFT_ROTATE: AB06.AH1(B0:AH1) AB07.AH1(B0:AH1) ; also sheet 4,7,9,10,11
DOUBLE_RIGHT_ROTATE: AB06.AD1(B0:AD1) AB07.AD1(B0:AD1) ; also sheet 4,7,9,10,11
GND [Supply]: AB06.AB2(B0:AB2) AB06.BB2(B0:BB2) AB06.BD1(B0:BD1) AB06.BF1(B0:BF1) AB06.BF2(B0:BF2) AB06.BH1(B0:BH1) AB07.AB2(B0:AB2) AB07.BB2(B0:BB2) AB07.BD1(B0:BD1) AB07.BE2(B1:BE2) AB07.BF1(B0:BF1) AB07.BF2(B0:BF2) AB07.BH1(B0:BH1) AB07.BN1(B1:BN1) AB07.BN2(B1:BN2) ; also sheet 1,3,9,10,11,12,13,14,15,16,19,20,21,23
INPUT_BUS00: AB07.BK1(B0:BK1) ; also sheet 12
INPUT_BUS01: AB07.BM1(B1:BM1) ; also sheet 12
INPUT_BUS02: AB06.BK1(B0:BK1) ; also sheet 12
IO_ENABLE: AB06.BL2(B0:BL2) AB07.BL2(B0:BL2) ; also sheet 3,5,9,10,11
LEFT_SHIFT: AB06.AF2(B0:AF2) AB07.AF2(B0:AF2) ; also sheet 4,7,9,10,11
MA_ENABLE(0-4): AB06.BP1(B0:BP1) AB07.BP1(B0:BP1) AB07.BR2(B1:BR2) ; also sheet 3,9
MEM00: AB07.BR1(B0:BR1) ; also sheet 2,16,23
MEM01: AB07.BV2(B1:BV2) ; also sheet 2,16,23
MEM02: AB06.BR1(B0:BR1) ; also sheet 2,16,23
MEM_ENABLE(0-4): AB06.BU2(B0:BU2) AB07.BU2(B0:BU2) AB07.BV1(B1:BV1) ; also sheet 3,4,9
N$109: AB06.BK2(B0:BK2) AB07.BJ1(B1:BJ1)
NO_SHIFT: AB06.AE1(B0:AE1) AB07.AE1(B0:AE1) ; also sheet 4,7,9,10,11
PC_ENABLE: AB06.BS2(B0:BS2) AB07.BS2(B0:BS2) ; also sheet 3,9,10,11
RIGHT_SHIFT: AB06.AD2(B0:AD2) AB07.AD2(B0:AD2) ; also sheet 4,7,9,10,11
SR00: A01.H2 AB07.BE1(B0:BE1)
SR01: A01.F2 AB07.BD2(B1:BD2)
SR02: A01.E2 AB06.BE1(B0:BE1)
SR_ENABLE: AB06.BC1(B0:BC1) AB07.BC1(B0:BC1) ; also sheet 3,9,10,11
Unconnected: AB07.AJ1 AB07.AK2 AB07.AN1 AB07.AP1 AB07.AP2 AB07.AR2

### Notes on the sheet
- Major Register Gating (Sheet 1)
- D-BS-8L-0-9

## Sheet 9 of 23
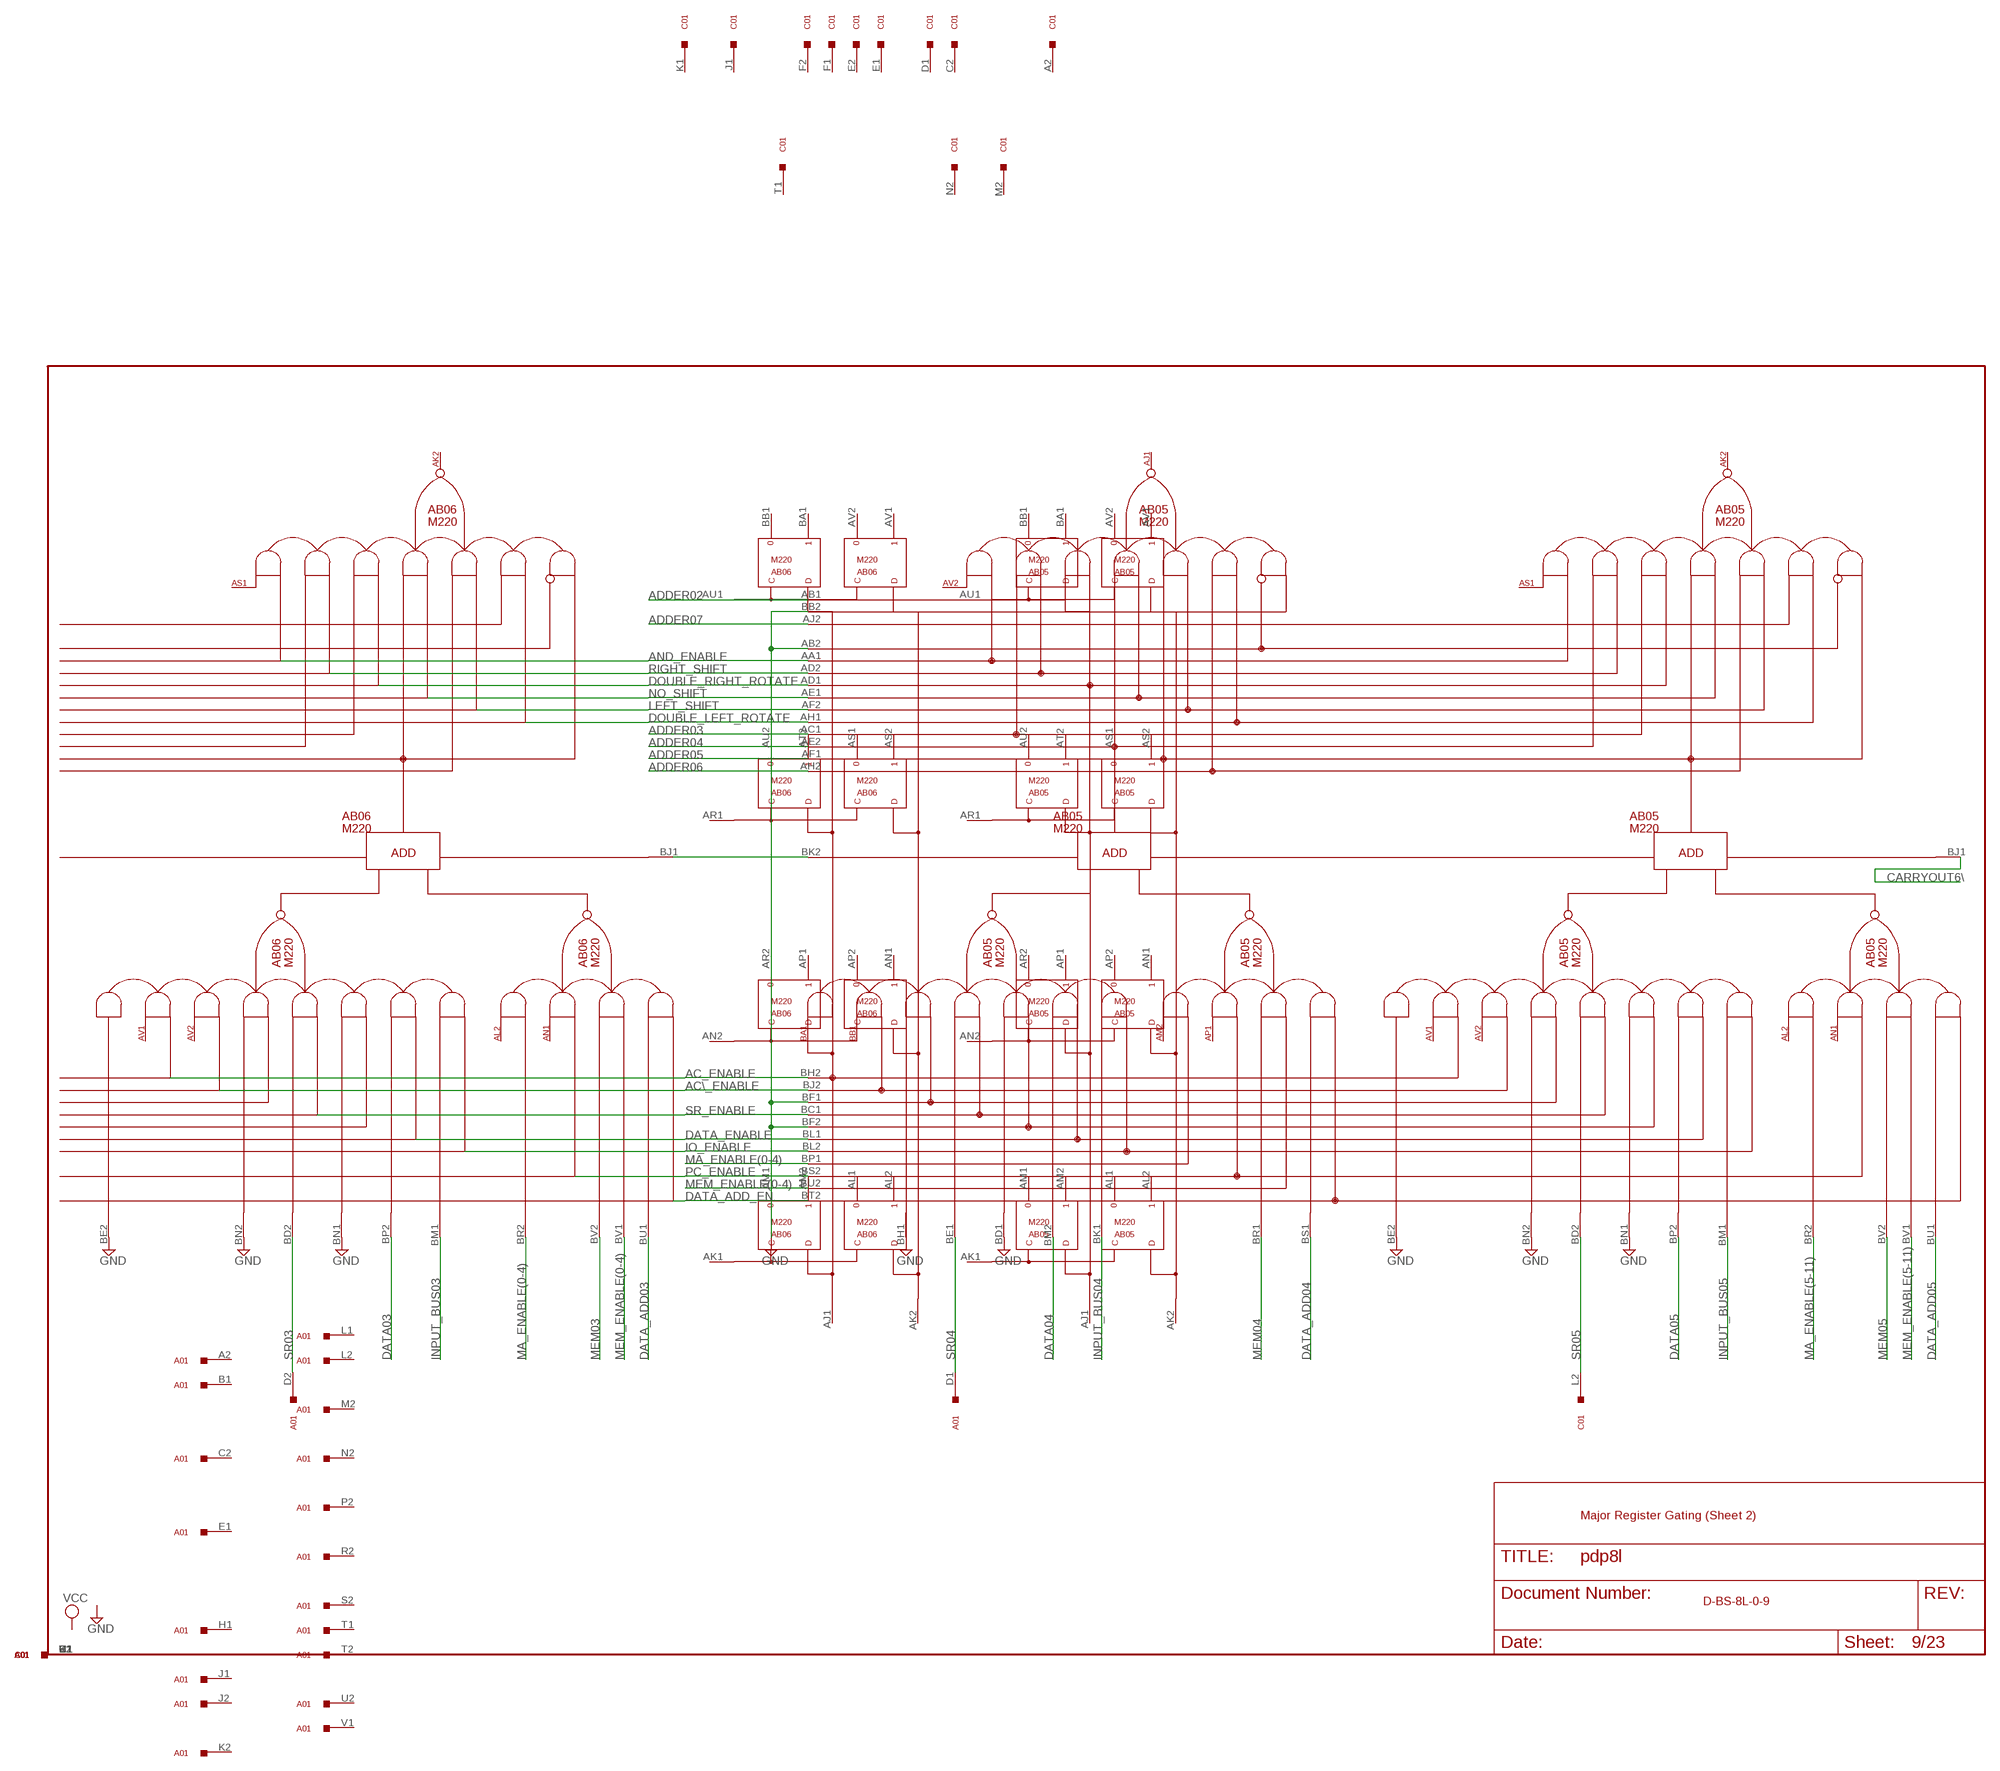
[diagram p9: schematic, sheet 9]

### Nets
AC\_ENABLE: AB05.BJ2(B0:BJ2) ; also sheet 3,8,10,11
AC_ENABLE: AB05.BH2(B0:BH2) ; also sheet 3,8,10,11
ADDER02: AB05.AB1(B0:AB1) ; also sheet 8
ADDER03: AB05.AC1(B0:AC1) ; also sheet 8
ADDER04: AB05.AE2(B0:AE2) ; also sheet 8,10
ADDER05: AB05.AF1(B0:AF1) ; also sheet 8,10
ADDER06: AB05.AH2(B0:AH2) ; also sheet 10
ADDER07: AB05.AJ2(B0:AJ2) ; also sheet 10
AND_ENABLE: AB05.AA1(B0:AA1) ; also sheet 4,8,10,11
CARRYOUT6\: AB05.BJ1(B1:BJ1) ; also sheet 10
DATA03: AB06.BP2(B1:BP2) ; also sheet 12
DATA04: AB05.BM2(B0:BM2) ; also sheet 12
DATA05: AB05.BP2(B1:BP2) ; also sheet 12
DATA_ADD03: AB06.BU1(B1:BU1) ; also sheet 12
DATA_ADD04: AB05.BS1(B0:BS1) ; also sheet 12
DATA_ADD05: AB05.BU1(B1:BU1) ; also sheet 12
DATA_ADD_EN: AB05.BT2(B0:BT2) ; also sheet 3,8,10,11
DATA_ENABLE: AB05.BL1(B0:BL1) ; also sheet 3,8,10,11
DOUBLE_LEFT_ROTATE: AB05.AH1(B0:AH1) ; also sheet 4,7,8,10,11
DOUBLE_RIGHT_ROTATE: AB05.AD1(B0:AD1) ; also sheet 4,7,8,10,11
GND [Supply]: AB05.AB2(B0:AB2) AB05.BB2(B0:BB2) AB05.BD1(B0:BD1) AB05.BE2(B1:BE2) AB05.BF1(B0:BF1) AB05.BF2(B0:BF2) AB05.BH1(B0:BH1) AB05.BN1(B1:BN1) AB05.BN2(B1:BN2) AB06.BE2(B1:BE2) AB06.BN1(B1:BN1) AB06.BN2(B1:BN2) ; also sheet 1,3,8,10,11,12,13,14,15,16,19,20,21,23
INPUT_BUS03: AB06.BM1(B1:BM1) ; also sheet 12
INPUT_BUS04: AB05.BK1(B0:BK1) ; also sheet 12
INPUT_BUS05: AB05.BM1(B1:BM1) ; also sheet 12
IO_ENABLE: AB05.BL2(B0:BL2) ; also sheet 3,5,8,10,11
LEFT_SHIFT: AB05.AF2(B0:AF2) ; also sheet 4,7,8,10,11
MA_ENABLE(0-4): AB05.BP1(B0:BP1) AB06.BR2(B1:BR2) ; also sheet 3,8
MA_ENABLE(5-11): AB05.BR2(B1:BR2) ; also sheet 3,10,11
MEM03: AB06.BV2(B1:BV2) ; also sheet 16,23
MEM04: AB05.BR1(B0:BR1) ; also sheet 16,23
MEM05: AB05.BV2(B1:BV2) ; also sheet 16,23
MEM_ENABLE(0-4): AB05.BU2(B0:BU2) AB06.BV1(B1:BV1) ; also sheet 3,4,8
MEM_ENABLE(5-11): AB05.BV1(B1:BV1) ; also sheet 3,10,11
N$110: AB05.BK2(B0:BK2) AB06.BJ1(B1:BJ1)
NO_SHIFT: AB05.AE1(B0:AE1) ; also sheet 4,7,8,10,11
PC_ENABLE: AB05.BS2(B0:BS2) ; also sheet 3,8,10,11
RIGHT_SHIFT: AB05.AD2(B0:AD2) ; also sheet 4,7,8,10,11
SR03: A01.D2 AB06.BD2(B1:BD2)
SR04: A01.D1 AB05.BE1(B0:BE1)
SR05: AB05.BD2(B1:BD2) C01.L2
SR_ENABLE: AB05.BC1(B0:BC1) ; also sheet 3,8,10,11
Unconnected: AB05.AJ1 AB05.AK2 AB05.AN1 AB05.AP1 AB05.AP2 AB05.AR2 AB06.AJ1 AB06.AK2 AB06.AN1 AB06.AP1 AB06.AP2 AB06.AR2

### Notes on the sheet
- Major Register Gating (Sheet 2)
- D-BS-8L-0-9

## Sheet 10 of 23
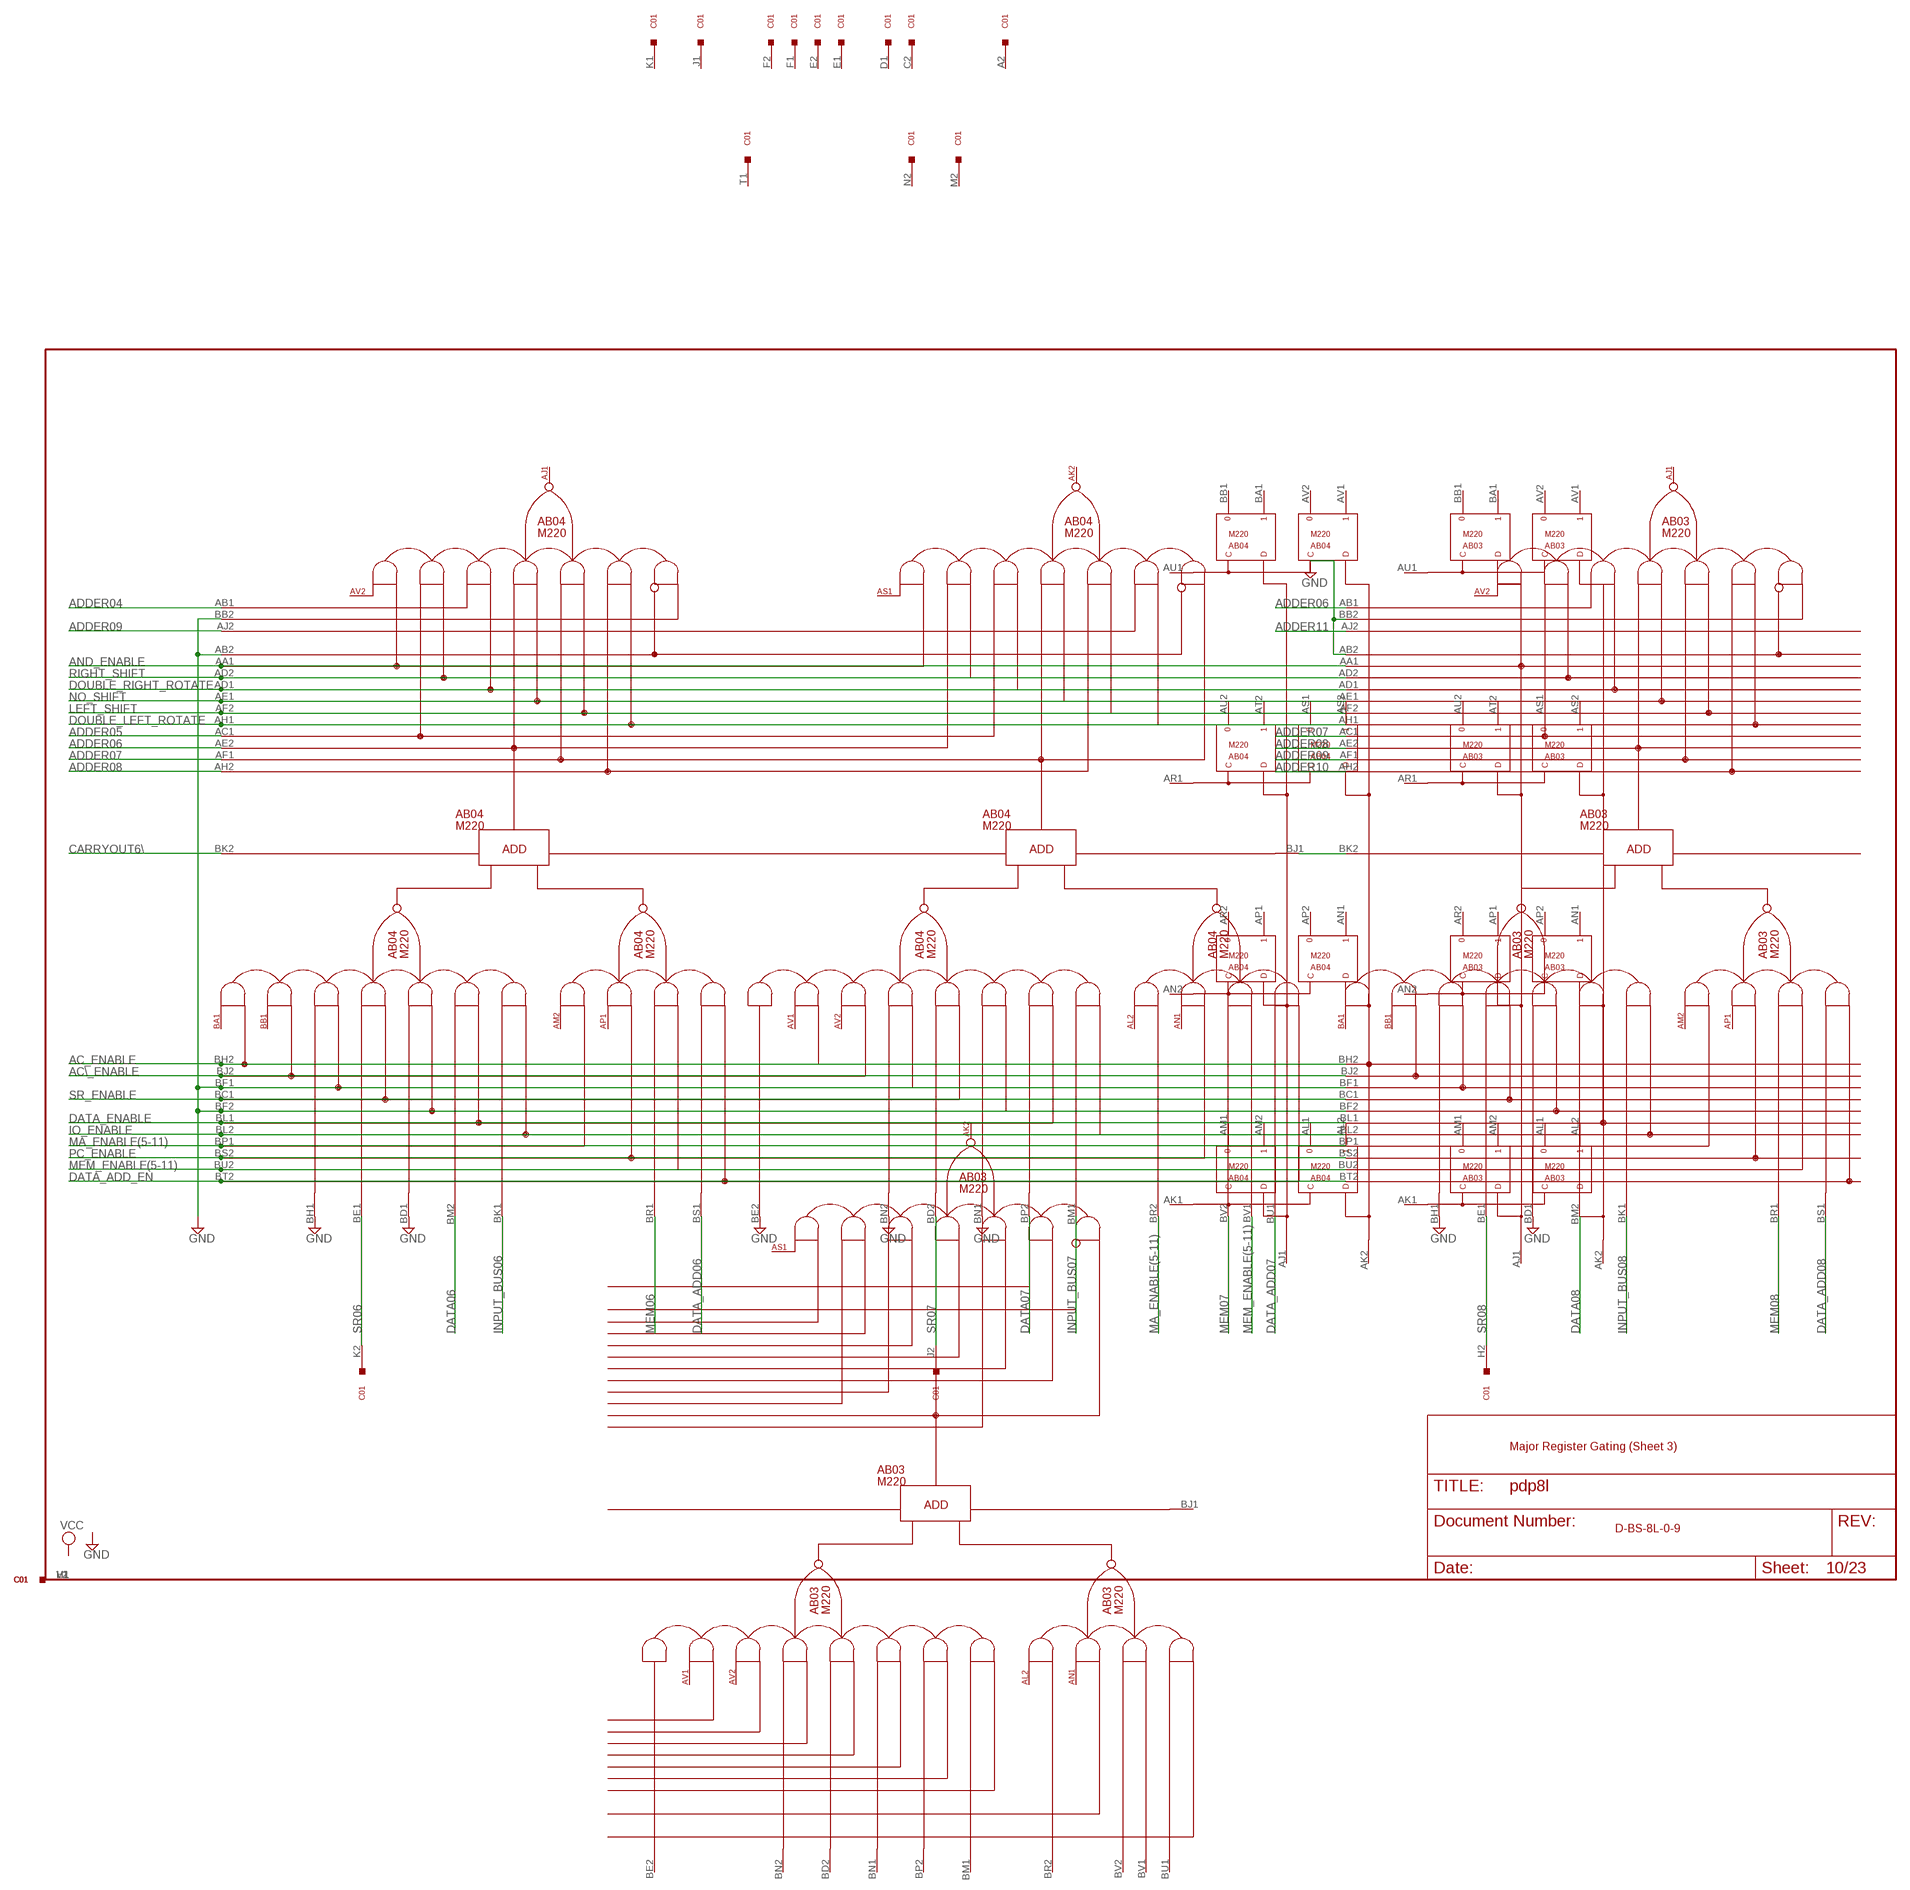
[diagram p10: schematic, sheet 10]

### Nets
AC\_ENABLE: AB03.BJ2(B0:BJ2) AB04.BJ2(B0:BJ2) ; also sheet 3,8,9,11
AC_ENABLE: AB03.BH2(B0:BH2) AB04.BH2(B0:BH2) ; also sheet 3,8,9,11
ADDER04: AB04.AB1(B0:AB1) ; also sheet 8,9
ADDER05: AB04.AC1(B0:AC1) ; also sheet 8,9
ADDER06: AB03.AB1(B0:AB1) AB04.AE2(B0:AE2) ; also sheet 9
ADDER07: AB03.AC1(B0:AC1) AB04.AF1(B0:AF1) ; also sheet 9
ADDER08: AB03.AE2(B0:AE2) AB04.AH2(B0:AH2) ; also sheet 11
ADDER09: AB03.AF1(B0:AF1) AB04.AJ2(B0:AJ2) ; also sheet 11
ADDER10: AB03.AH2(B0:AH2) ; also sheet 7,11
ADDER11: AB03.AJ2(B0:AJ2) ; also sheet 7,8,11
AND_ENABLE: AB03.AA1(B0:AA1) AB04.AA1(B0:AA1) ; also sheet 4,8,9,11
CARRYOUT6\: AB04.BK2(B0:BK2) ; also sheet 9
DATA06: AB04.BM2(B0:BM2) ; also sheet 12
DATA07: AB04.BP2(B1:BP2) ; also sheet 12
DATA08: AB03.BM2(B0:BM2) ; also sheet 12
DATA_ADD06: AB04.BS1(B0:BS1) ; also sheet 12
DATA_ADD07: AB04.BU1(B1:BU1) ; also sheet 12
DATA_ADD08: AB03.BS1(B0:BS1) ; also sheet 12
DATA_ADD_EN: AB03.BT2(B0:BT2) AB04.BT2(B0:BT2) ; also sheet 3,8,9,11
DATA_ENABLE: AB03.BL1(B0:BL1) AB04.BL1(B0:BL1) ; also sheet 3,8,9,11
DOUBLE_LEFT_ROTATE: AB03.AH1(B0:AH1) AB04.AH1(B0:AH1) ; also sheet 4,7,8,9,11
DOUBLE_RIGHT_ROTATE: AB03.AD1(B0:AD1) AB04.AD1(B0:AD1) ; also sheet 4,7,8,9,11
GND [Supply]: AB03.AB2(B0:AB2) AB03.BB2(B0:BB2) AB03.BD1(B0:BD1) AB03.BF1(B0:BF1) AB03.BF2(B0:BF2) AB03.BH1(B0:BH1) AB04.AB2(B0:AB2) AB04.BB2(B0:BB2) AB04.BD1(B0:BD1) AB04.BE2(B1:BE2) AB04.BF1(B0:BF1) AB04.BF2(B0:BF2) AB04.BH1(B0:BH1) AB04.BN1(B1:BN1) AB04.BN2(B1:BN2) ; also sheet 1,3,8,9,11,12,13,14,15,16,19,20,21,23
INPUT_BUS06: AB04.BK1(B0:BK1) ; also sheet 12
INPUT_BUS07: AB04.BM1(B1:BM1) ; also sheet 12
INPUT_BUS08: AB03.BK1(B0:BK1) ; also sheet 12
IO_ENABLE: AB03.BL2(B0:BL2) AB04.BL2(B0:BL2) ; also sheet 3,5,8,9,11
LEFT_SHIFT: AB03.AF2(B0:AF2) AB04.AF2(B0:AF2) ; also sheet 4,7,8,9,11
MA_ENABLE(5-11): AB03.BP1(B0:BP1) AB04.BP1(B0:BP1) AB04.BR2(B1:BR2) ; also sheet 3,9,11
MEM06: AB04.BR1(B0:BR1) ; also sheet 16,23
MEM07: AB04.BV2(B1:BV2) ; also sheet 16,23
MEM08: AB03.BR1(B0:BR1) ; also sheet 16,23
MEM_ENABLE(5-11): AB03.BU2(B0:BU2) AB04.BU2(B0:BU2) AB04.BV1(B1:BV1) ; also sheet 3,9,11
N$111: AB03.BK2(B0:BK2) AB04.BJ1(B1:BJ1)
NO_SHIFT: AB03.AE1(B0:AE1) AB04.AE1(B0:AE1) ; also sheet 4,7,8,9,11
PC_ENABLE: AB03.BS2(B0:BS2) AB04.BS2(B0:BS2) ; also sheet 3,8,9,11
RIGHT_SHIFT: AB03.AD2(B0:AD2) AB04.AD2(B0:AD2) ; also sheet 4,7,8,9,11
SR06: AB04.BE1(B0:BE1) C01.K2
SR07: AB04.BD2(B1:BD2) C01.J2
SR08: AB03.BE1(B0:BE1) C01.H2
SR_ENABLE: AB03.BC1(B0:BC1) AB04.BC1(B0:BC1) ; also sheet 3,8,9,11
Unconnected: AB04.AJ1 AB04.AK2 AB04.AN1 AB04.AP1 AB04.AP2 AB04.AR2

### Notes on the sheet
- Major Register Gating (Sheet 3)
- D-BS-8L-0-9

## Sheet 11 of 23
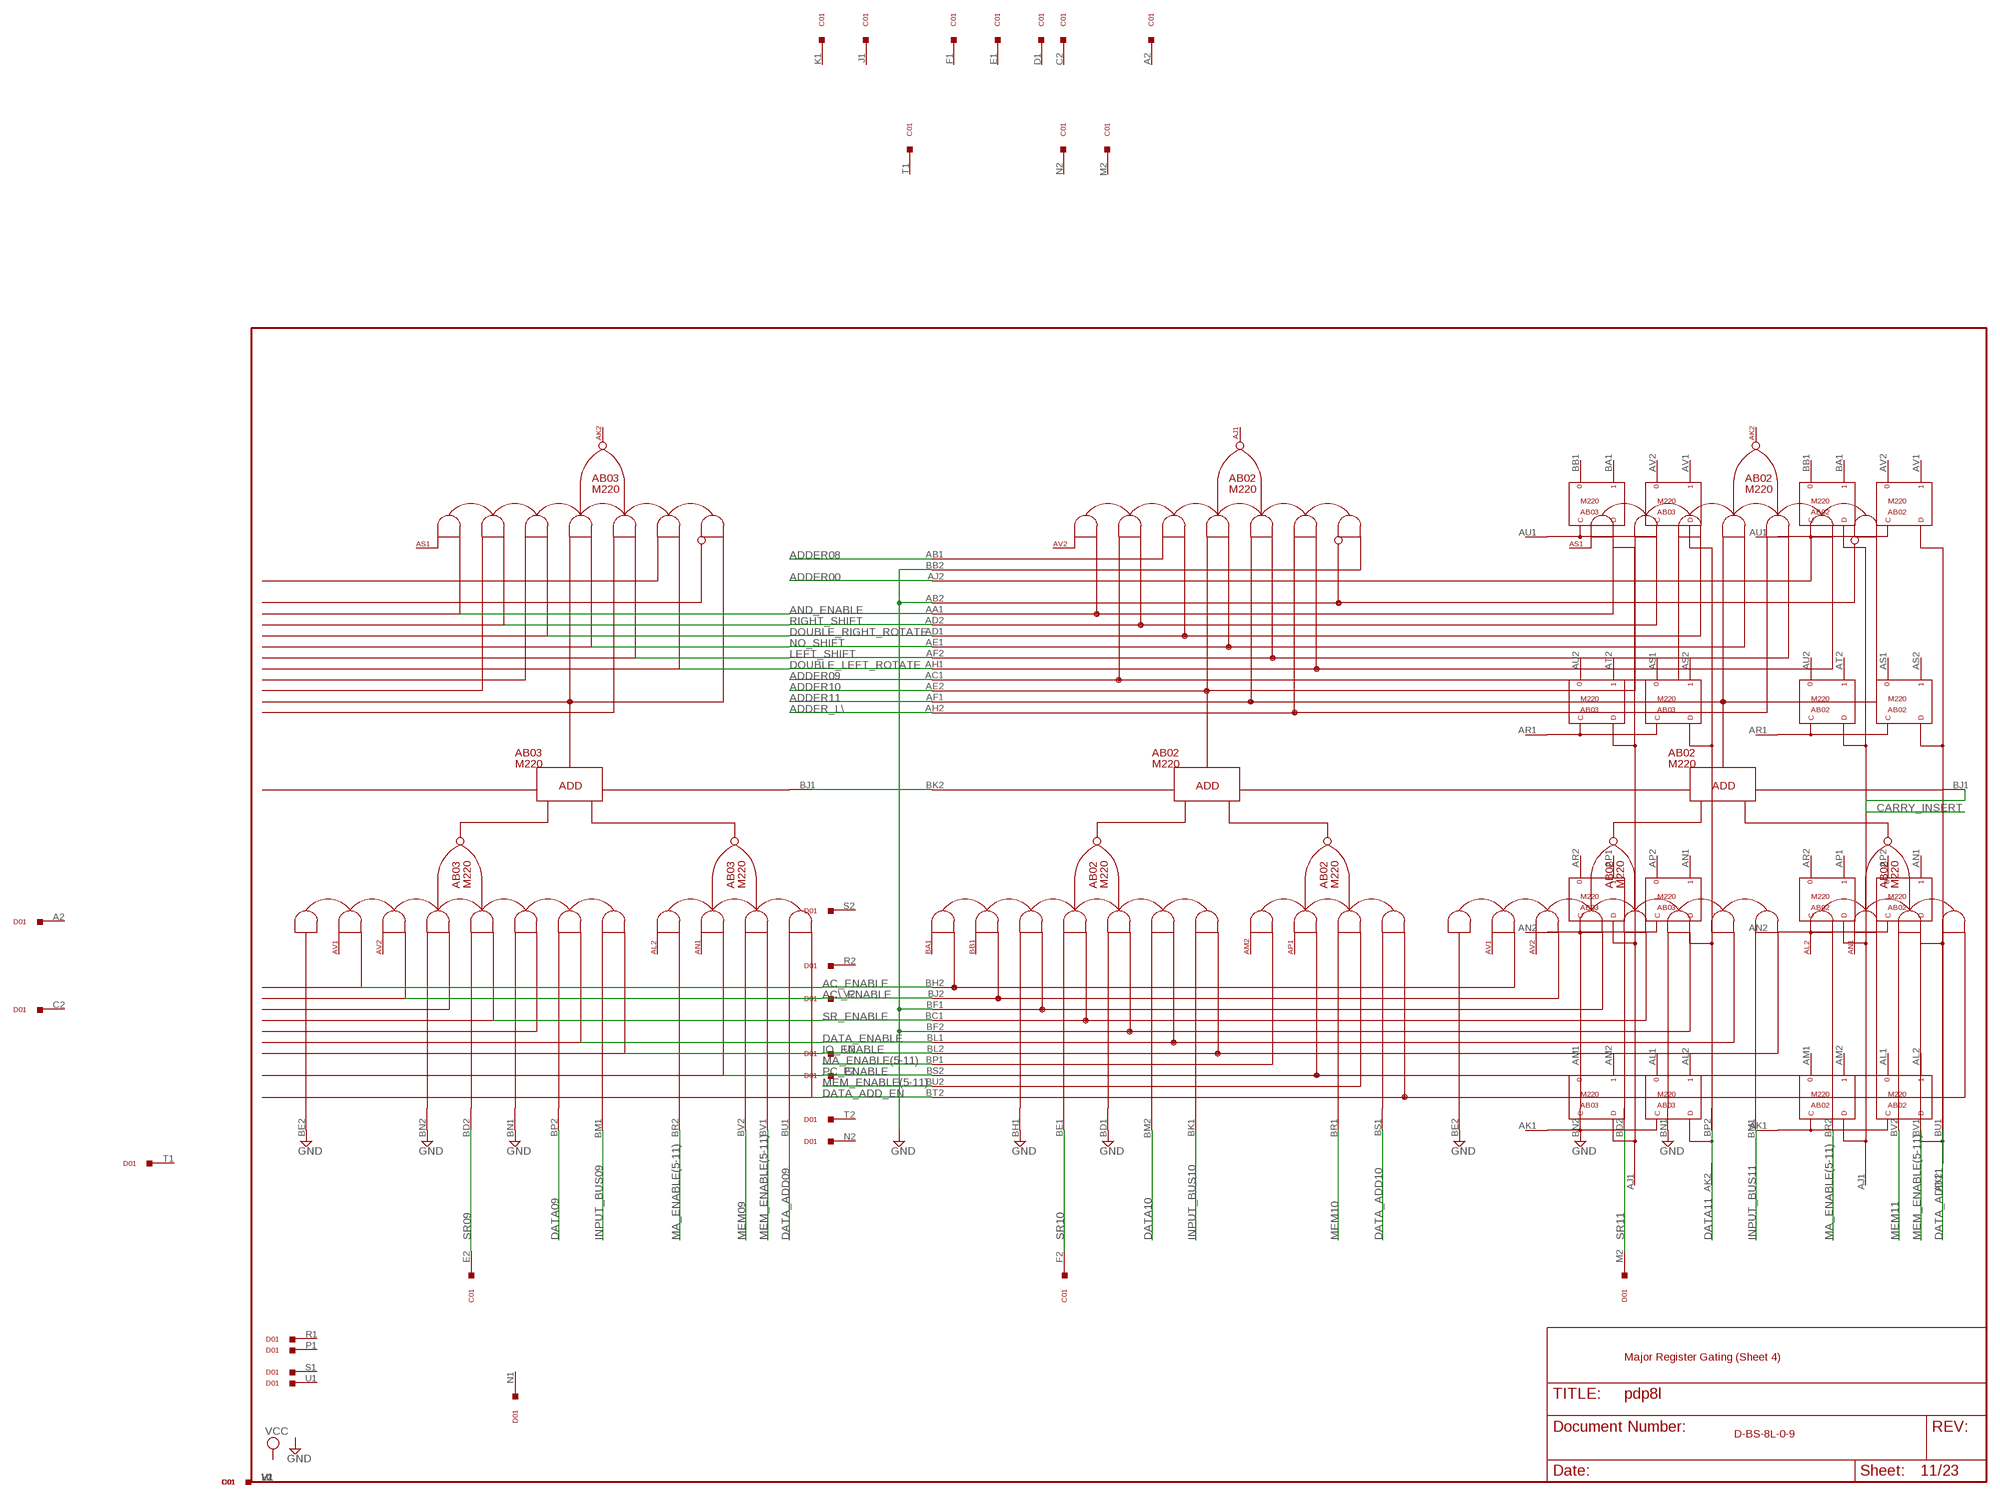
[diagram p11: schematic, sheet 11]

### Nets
AC\_ENABLE: AB02.BJ2(B0:BJ2) ; also sheet 3,8,9,10
AC_ENABLE: AB02.BH2(B0:BH2) ; also sheet 3,8,9,10
ADDER00: AB02.AJ2(B0:AJ2) ; also sheet 7,8
ADDER08: AB02.AB1(B0:AB1) ; also sheet 10
ADDER09: AB02.AC1(B0:AC1) ; also sheet 10
ADDER10: AB02.AE2(B0:AE2) ; also sheet 7,10
ADDER11: AB02.AF1(B0:AF1) ; also sheet 7,8,10
ADDER_L\: AB02.AH2(B0:AH2) ; also sheet 7,8
AND_ENABLE: AB02.AA1(B0:AA1) ; also sheet 4,8,9,10
CARRY_INSERT: AB02.BJ1(B1:BJ1) ; also sheet 4
DATA09: AB03.BP2(B1:BP2) ; also sheet 12
DATA10: AB02.BM2(B0:BM2) ; also sheet 12
DATA11: AB02.BP2(B1:BP2) ; also sheet 12
DATA_ADD09: AB03.BU1(B1:BU1) ; also sheet 12
DATA_ADD10: AB02.BS1(B0:BS1) ; also sheet 12
DATA_ADD11: AB02.BU1(B1:BU1) ; also sheet 12
DATA_ADD_EN: AB02.BT2(B0:BT2) ; also sheet 3,8,9,10
DATA_ENABLE: AB02.BL1(B0:BL1) ; also sheet 3,8,9,10
DOUBLE_LEFT_ROTATE: AB02.AH1(B0:AH1) ; also sheet 4,7,8,9,10
DOUBLE_RIGHT_ROTATE: AB02.AD1(B0:AD1) ; also sheet 4,7,8,9,10
GND [Supply]: AB02.AB2(B0:AB2) AB02.BB2(B0:BB2) AB02.BD1(B0:BD1) AB02.BE2(B1:BE2) AB02.BF1(B0:BF1) AB02.BF2(B0:BF2) AB02.BH1(B0:BH1) AB02.BN1(B1:BN1) AB02.BN2(B1:BN2) AB03.BE2(B1:BE2) AB03.BN1(B1:BN1) AB03.BN2(B1:BN2) ; also sheet 1,3,8,9,10,12,13,14,15,16,19,20,21,23
INPUT_BUS09: AB03.BM1(B1:BM1) ; also sheet 12
INPUT_BUS10: AB02.BK1(B0:BK1) ; also sheet 12
INPUT_BUS11: AB02.BM1(B1:BM1) ; also sheet 12
IO_ENABLE: AB02.BL2(B0:BL2) ; also sheet 3,5,8,9,10
LEFT_SHIFT: AB02.AF2(B0:AF2) ; also sheet 4,7,8,9,10
MA_ENABLE(5-11): AB02.BP1(B0:BP1) AB02.BR2(B1:BR2) AB03.BR2(B1:BR2) ; also sheet 3,9,10
MEM09: AB03.BV2(B1:BV2) ; also sheet 16,23
MEM10: AB02.BR1(B0:BR1) ; also sheet 16,23
MEM11: AB02.BV2(B1:BV2) ; also sheet 16,23
MEM_ENABLE(5-11): AB02.BU2(B0:BU2) AB02.BV1(B1:BV1) AB03.BV1(B1:BV1) ; also sheet 3,9,10
N$112: AB02.BK2(B0:BK2) AB03.BJ1(B1:BJ1)
NO_SHIFT: AB02.AE1(B0:AE1) ; also sheet 4,7,8,9,10
PC_ENABLE: AB02.BS2(B0:BS2) ; also sheet 3,8,9,10
RIGHT_SHIFT: AB02.AD2(B0:AD2) ; also sheet 4,7,8,9,10
SR09: AB03.BD2(B1:BD2) C01.E2
SR10: AB02.BE1(B0:BE1) C01.F2
SR11: AB02.BD2(B1:BD2) D01.M2
SR_ENABLE: AB02.BC1(B0:BC1) ; also sheet 3,8,9,10
Unconnected: AB02.AJ1 AB02.AK2 AB02.AN1 AB02.AP1 AB02.AP2 AB02.AR2 AB03.AJ1 AB03.AK2 AB03.AN1 AB03.AP1 AB03.AP2 AB03.AR2

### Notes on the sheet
- Major Register Gating (Sheet 4)
- D-BS-8L-0-9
